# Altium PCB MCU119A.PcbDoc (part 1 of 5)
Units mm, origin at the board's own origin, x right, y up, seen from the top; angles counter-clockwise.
Board outline 58.62 x 144.37 mm, 6 copper layers (Top Signal, GND, Middle Signal, PWR, GND2, Bottom Signal), stack 1.566 mm thick; 316 components, 238 nets, 1210 pads, 1064 vias.
Unrouted connection lines stored in the file: 59.
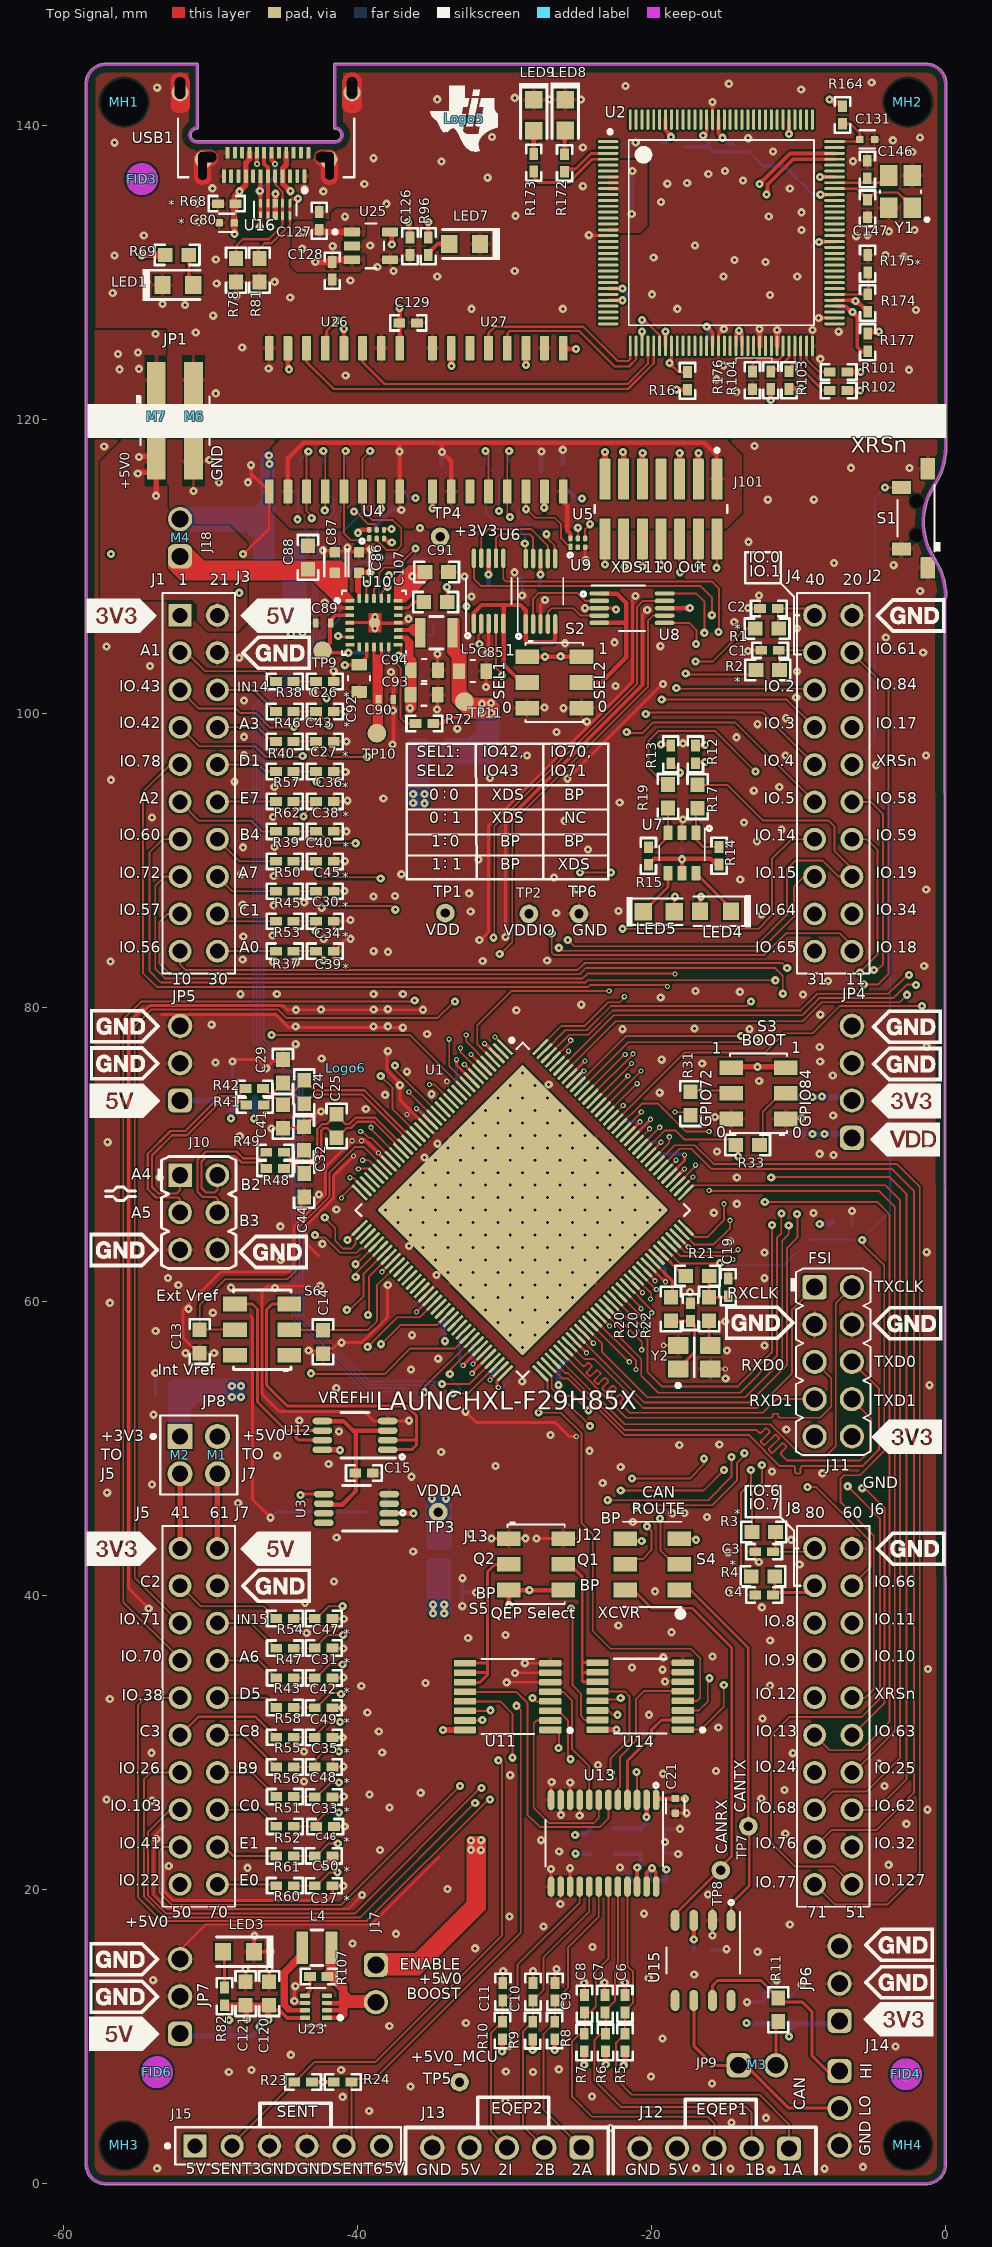
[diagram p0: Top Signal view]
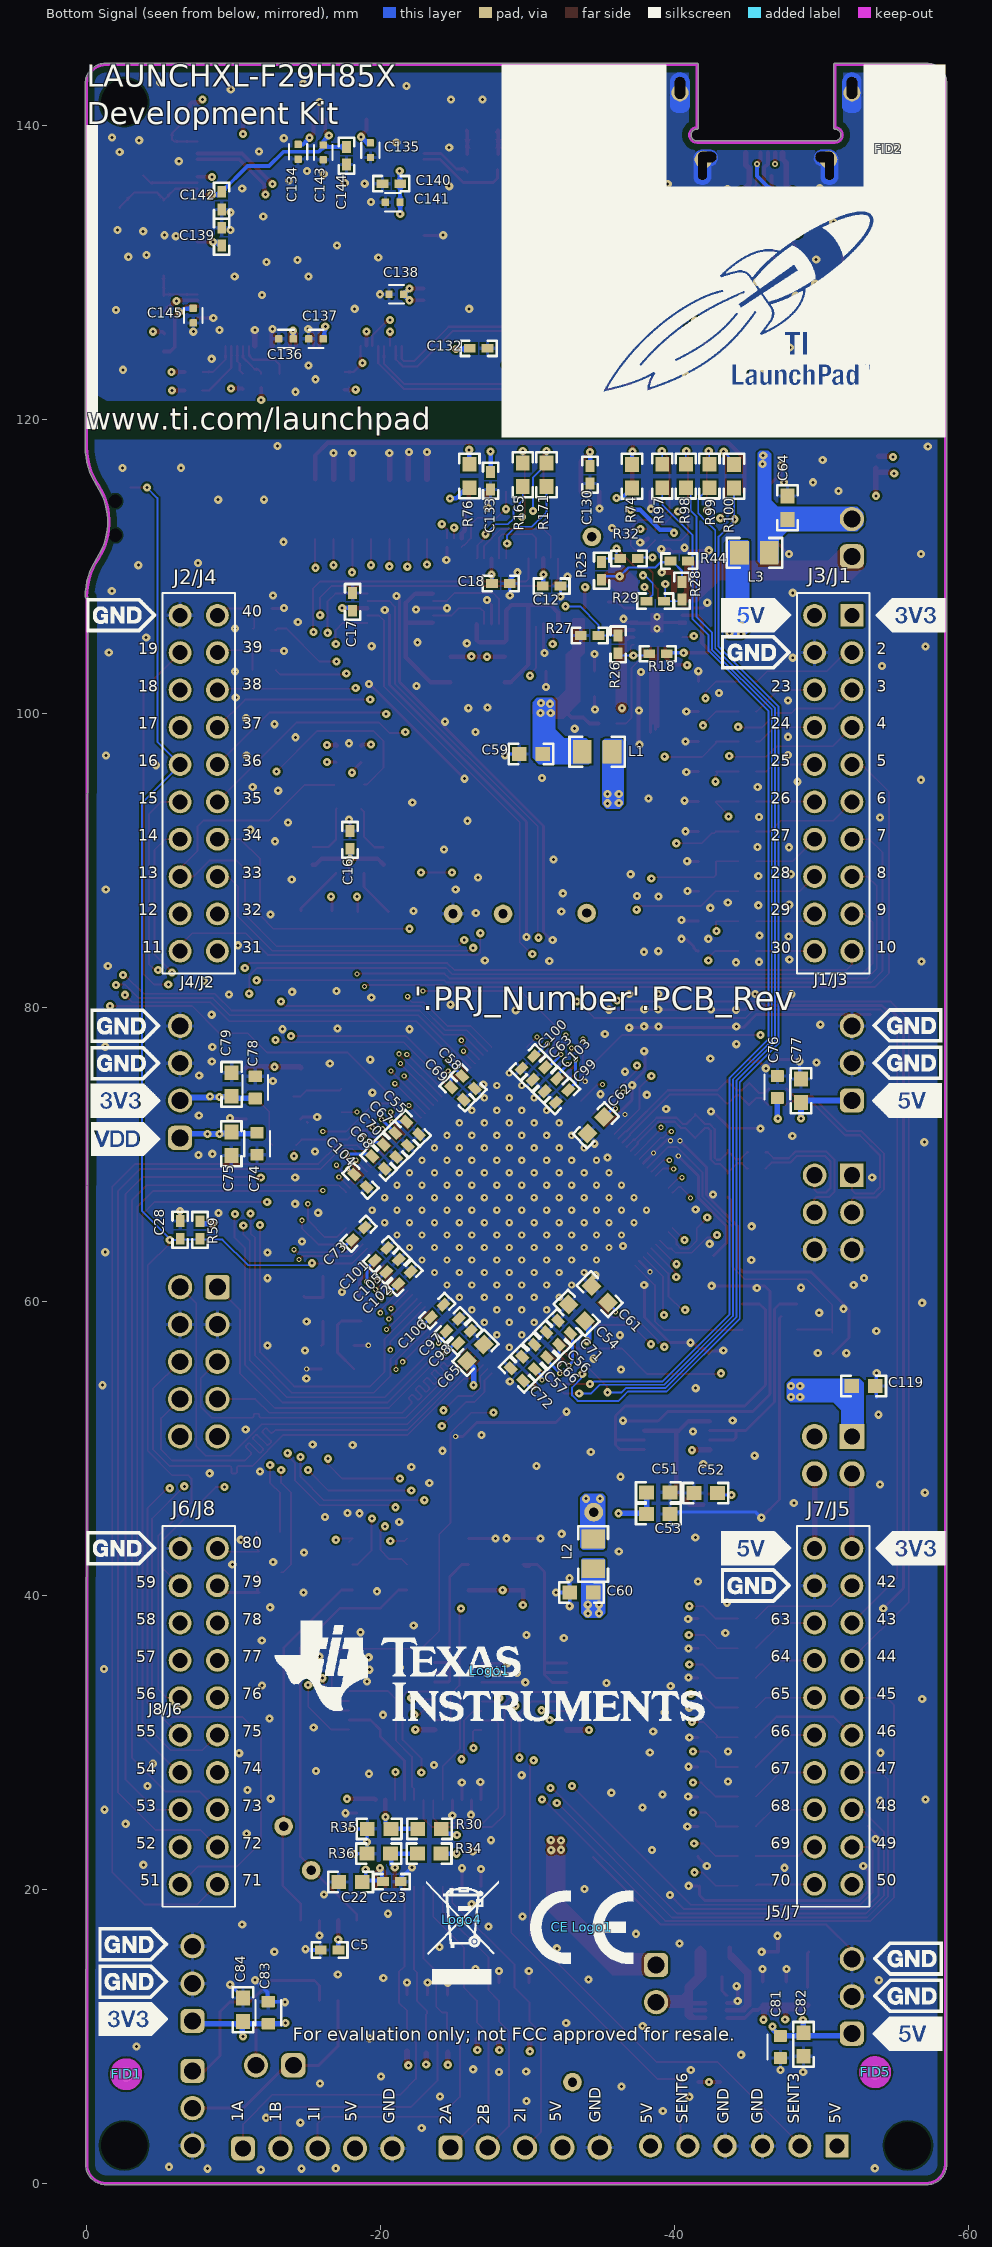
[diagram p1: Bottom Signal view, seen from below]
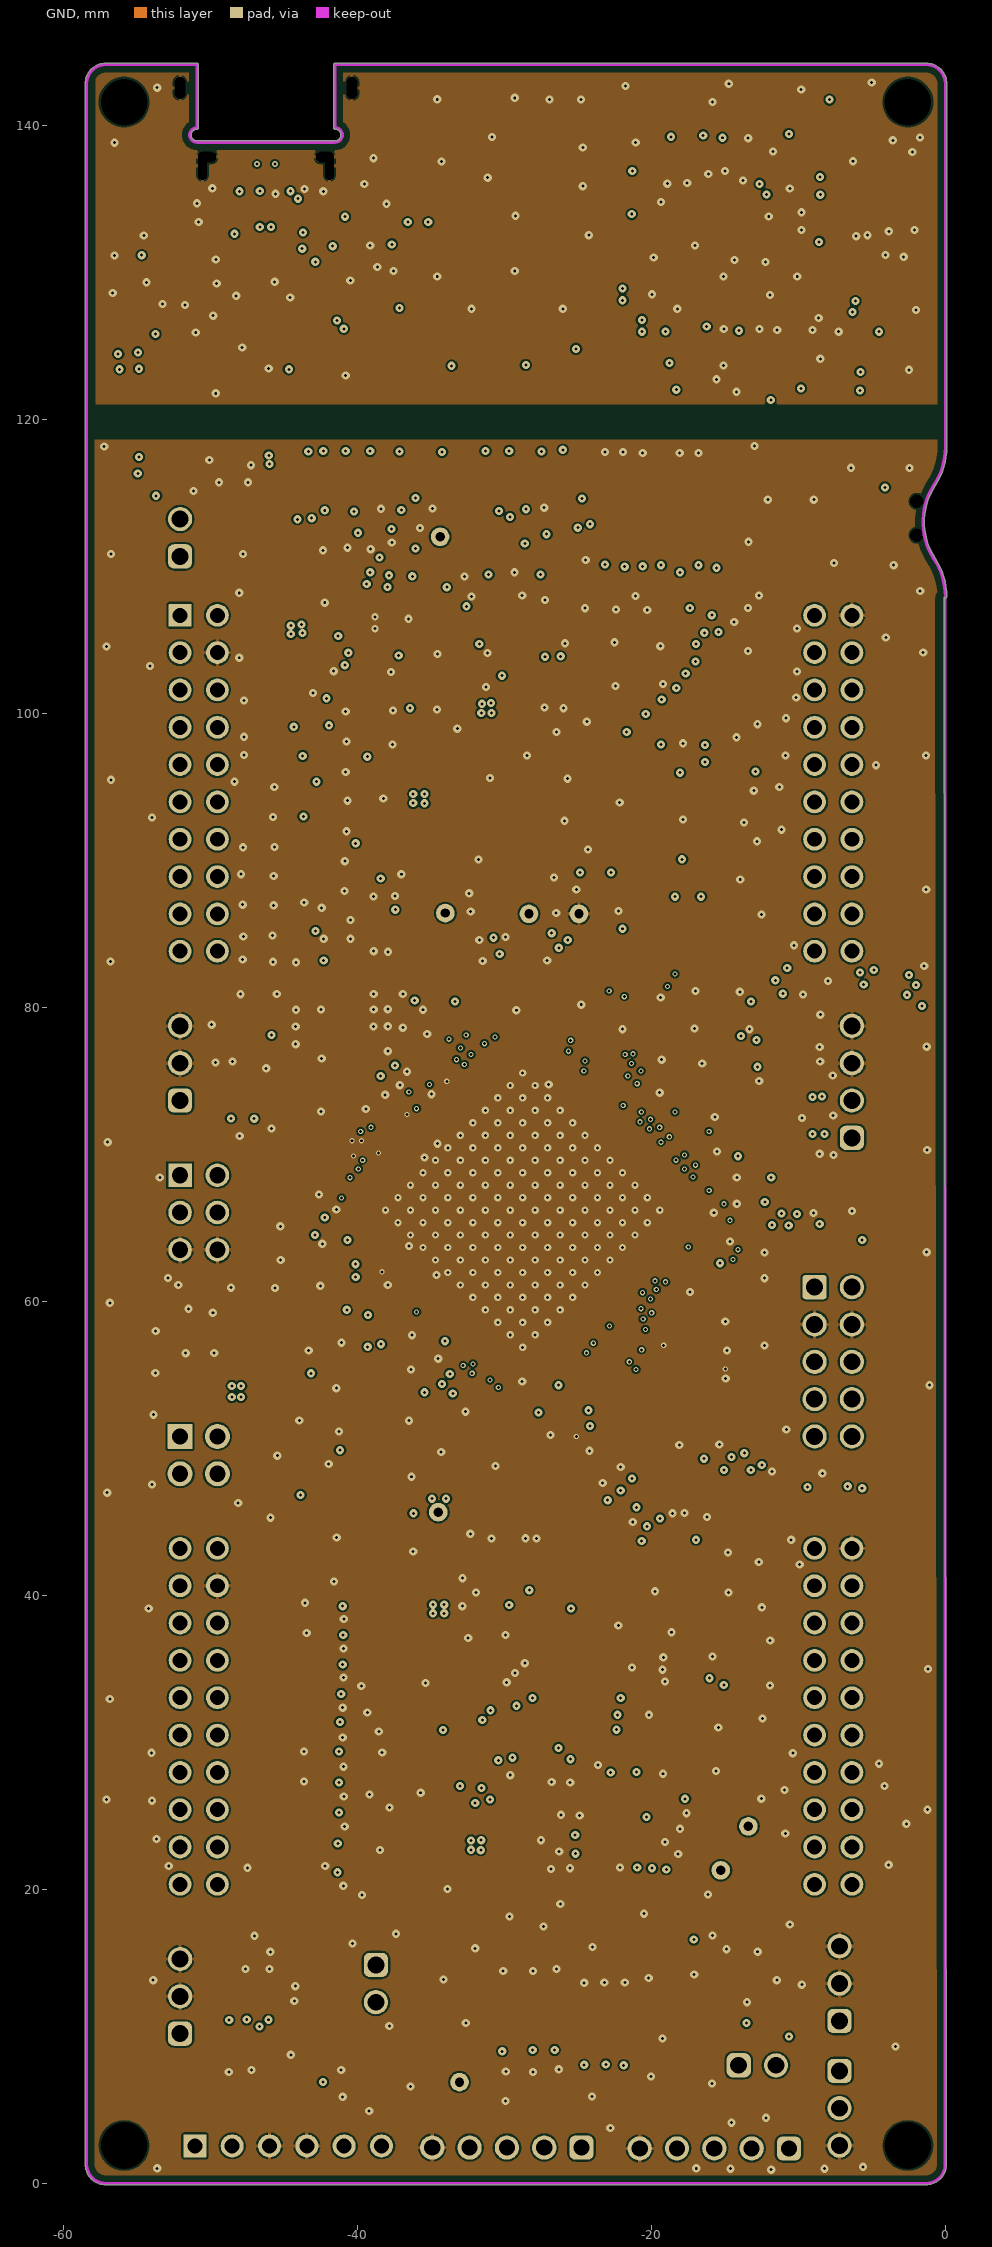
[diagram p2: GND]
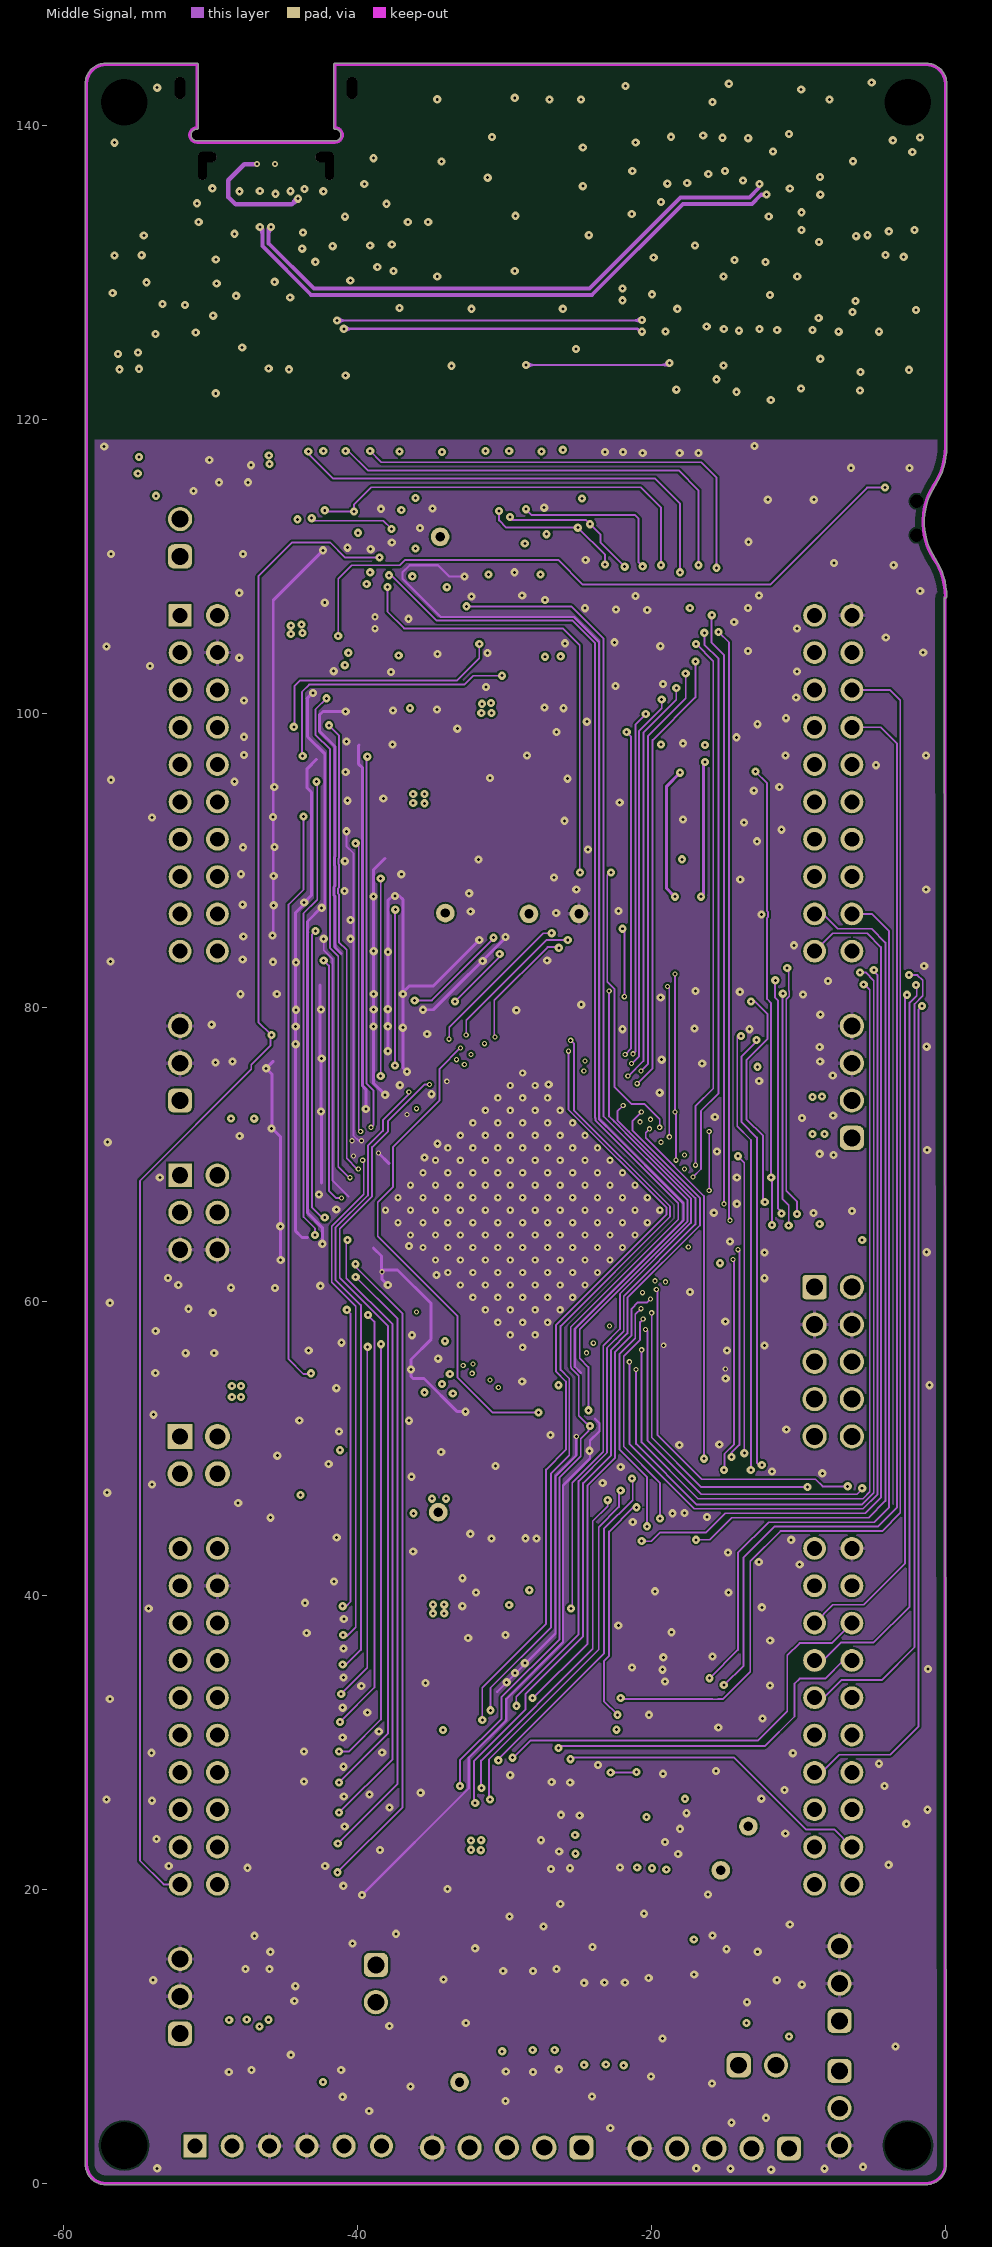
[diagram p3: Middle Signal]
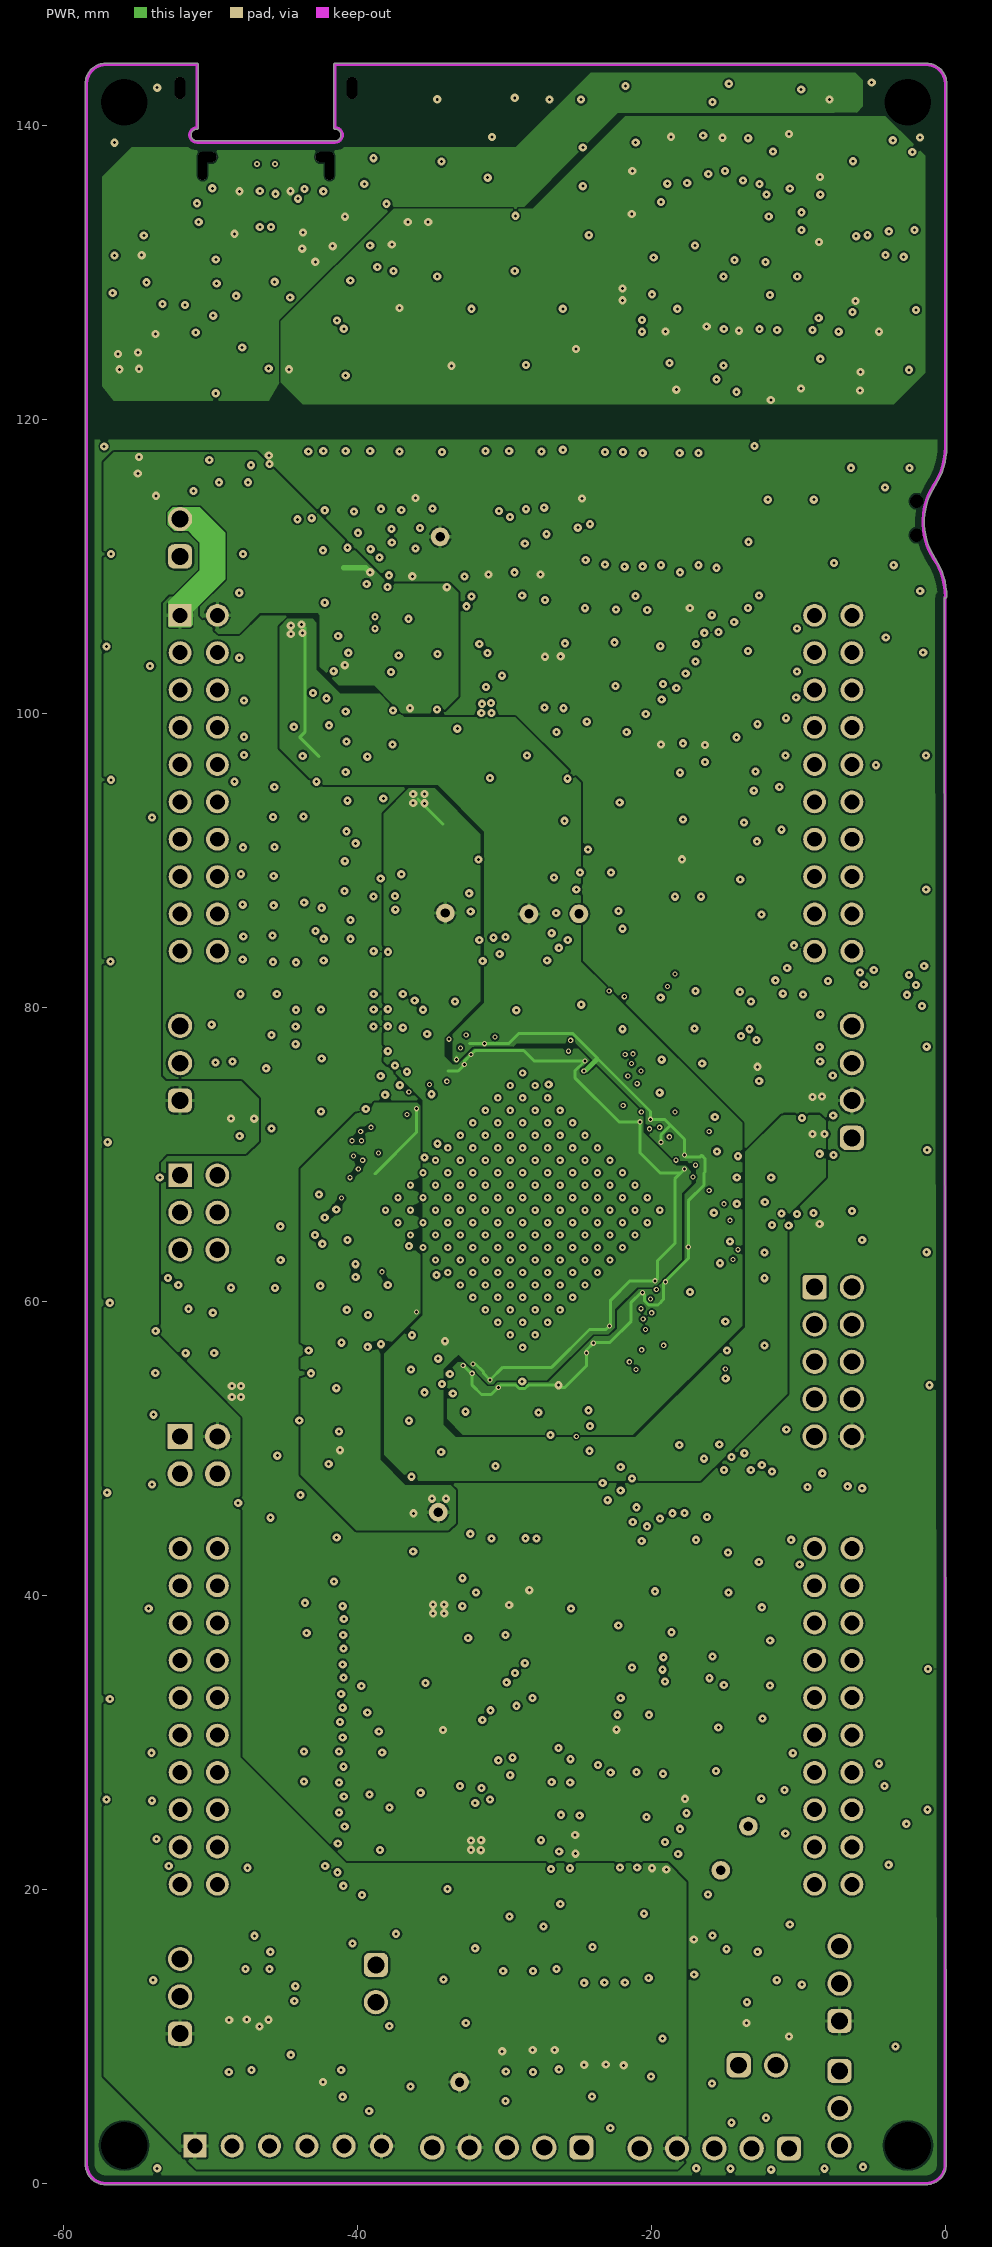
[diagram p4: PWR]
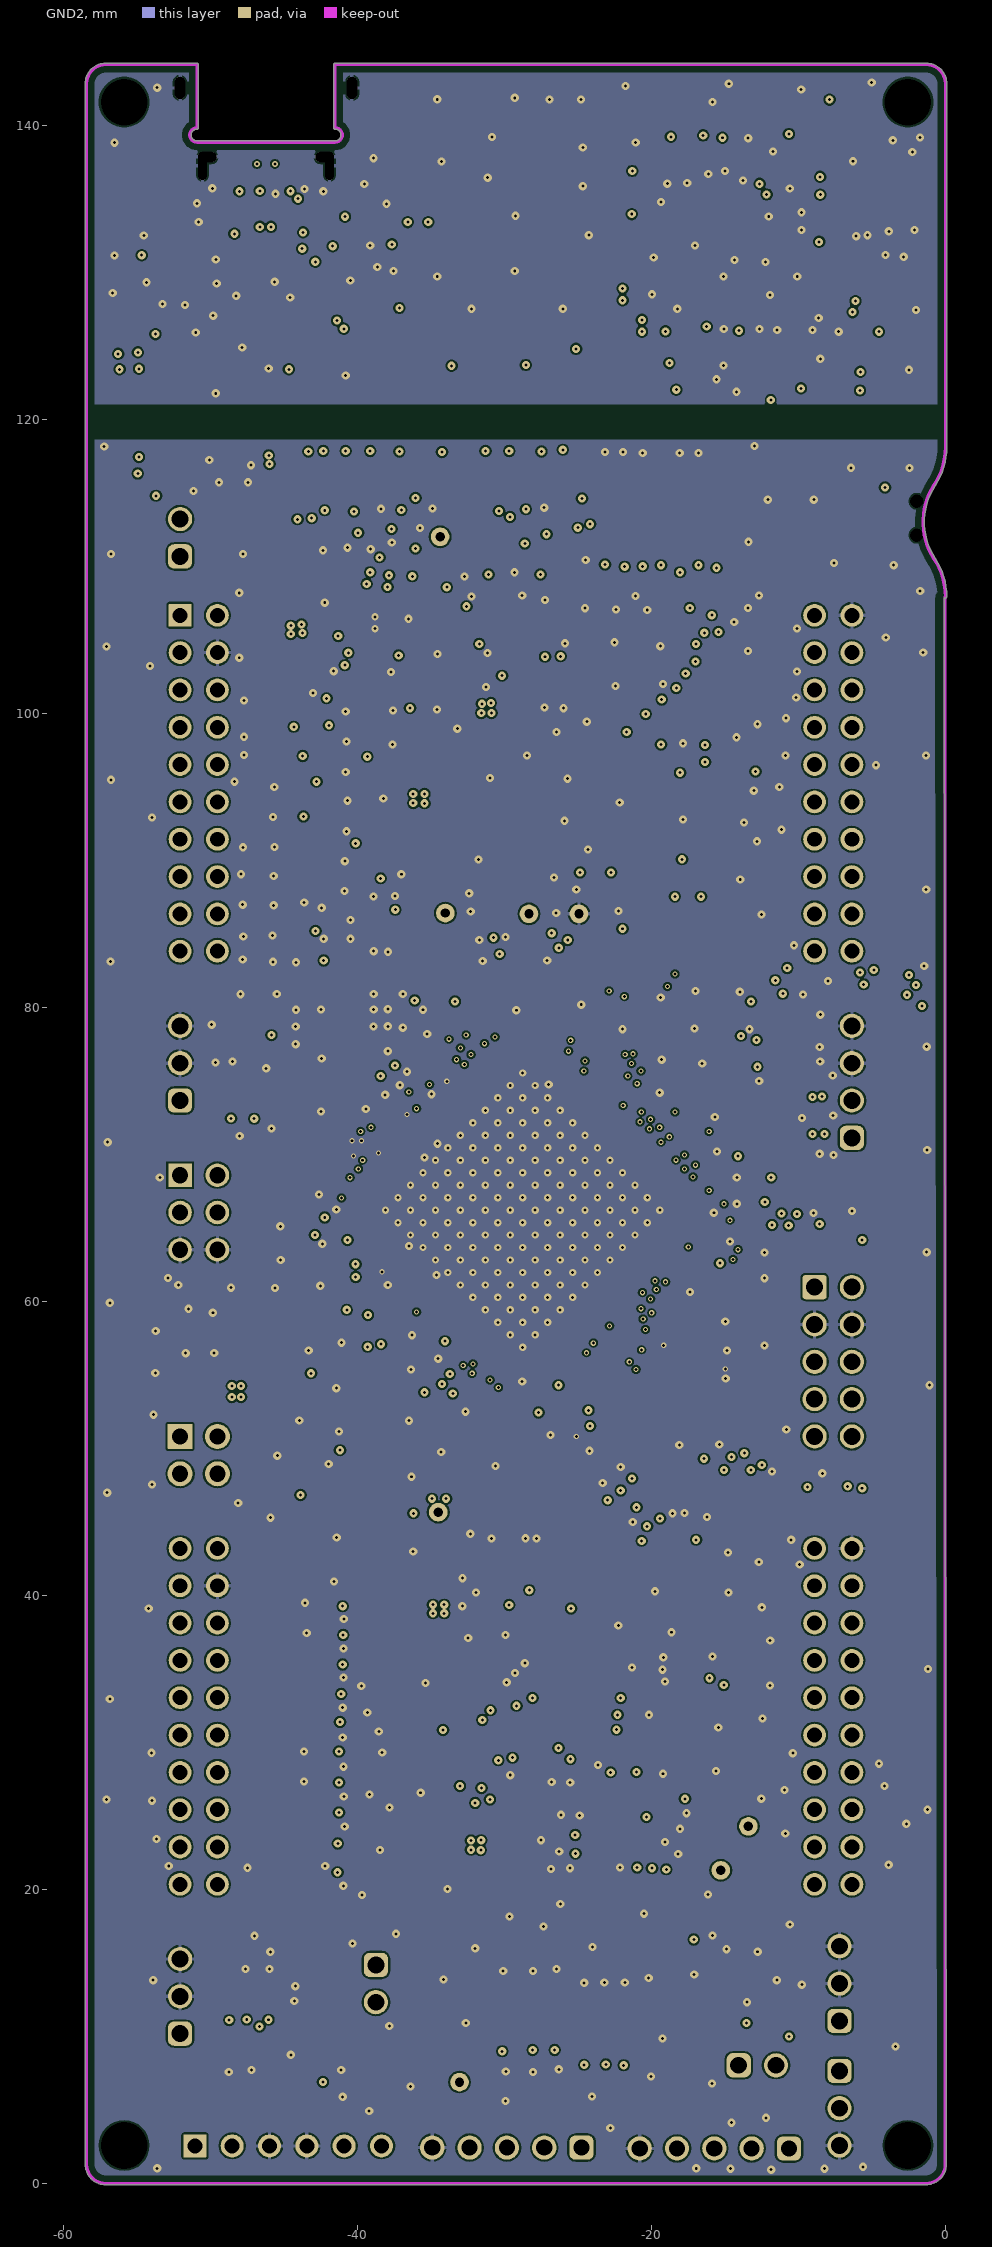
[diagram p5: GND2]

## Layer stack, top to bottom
Top Solder: solder mask 0.0102, Solder Resist, Dk 3.5
Top Signal: signal copper 0.0356
Dielectric 1: prepreg 0.1588, FR-4, Dk 4.2
GND: signal copper 0.0356
Dielectric 2: core 0.4089, FR-4, Dk 4.2
Middle Signal: signal copper 0.0356
Dielectric 3: prepreg 0.2169, FR-4, Dk 4.2
PWR: signal copper 0.0356
Dielectric 4: core 0.4089, FR-4, Dk 4.2
GND2: signal copper 0.0356
Dielectric 5: prepreg 0.1588, FR-4, Dk 4.2
Bottom Signal: signal copper 0.0356
Bottom Solder: solder mask 0.0102, Solder Resist, Dk 3.5

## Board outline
-57.141,-0.1 cw(c-57.141,1.27) -58.511,1.268 -58.511,1.27 -58.511,142.895 cw(c-57.141,142.895) -57.141,144.265 -50.911,144.265 cw(c-50.911,144.165) -50.811,144.165 -50.811,139.885 cw(c-50.911,139.885) -50.911,139.785 ccw(c-50.911,139.385) -51.311,139.385 ccw(c-50.911,139.385) -50.911,138.985 -41.511,138.985 -41.51,138.985 ccw(c-41.511,139.385) -41.111,139.385 ccw(c-41.511,139.385) -41.511,139.785 cw(c-41.511,139.885) -41.611,139.885 -41.611,144.135 -41.61,144.15 cw(c-41.511,144.165) -41.511,144.265 -1.261,144.265 cw(c-1.261,142.895) 0.109,142.895 0.109,118.13 cw(c-4.605,118.13) -0.669,115.535 ccw(c3.099,113.05) -0.669,110.565 cw(c-4.605,107.97) 0.109,107.97 cw(c0.009,107.97) -0.043,107.884 0.078,1.27 cw(c-1.292,1.27) -1.29,-0.1 -1.292,-0.1

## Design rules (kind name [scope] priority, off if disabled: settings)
AcuteAngle [All] p1: minimum=4.50000000000000E+0001 checktracksonly=TRUE
AcuteAngle AcuteAngle_poly [InPolygon] p2: minimum=4.50000000000000E+0001 checktracksonly=FALSE
AssemblyTestPointUsage [All] p1: valid=2
BoardOutlineClearance BoardOutlineClearance_USB1 [InComponent('USB1')] p1: gap=0 ignorepadtopadclearanceinfootprint=FALSE
BoardOutlineClearance BoardOutlineClearance_MountingHoles [OnCopper and InComponentClass('Mounting Holes')] p2: gap=1.016 ignorepadtopadclearanceinfootprint=FALSE
BoardOutlineClearance BoardOutlineClearance_Poly [OnCopper and IsPoly] p3: gap=0.635 ignorepadtopadclearanceinfootprint=FALSE
BoardOutlineClearance [OnCopper and Not InComponentClass('Logo') and not InComponentClass('FiducialMark') and not InRegion(1000,500,4000,800) and not InPoly] p4: gap=0.254 ignorepadtopadclearanceinfootprint=FALSE
Clearance Clearance_1 [InComponent('S1')OR InComponent('USB1') vs OnLayer('Keep-Out Layer')] p1: gap=0 ignorepadtopadclearanceinfootprint=FALSE
Clearance Poly [InPolygon] p2: gap=0.127 ignorepadtopadclearanceinfootprint=FALSE
Clearance "RJ45 pad" [InComponent('RJ1') OR InComponent('RJ2')] p3: gap=0.127 ignorepadtopadclearanceinfootprint=TRUE except(0: SMDPad-THPad)
Clearance Keepout [((IsTrack Or IsArc) And Not InPoly) And IsFree and IsKeepOut vs ((IsTrack Or IsArc) And Not InPoly) And IsFree and IsKeepOut] p4: gap=0.127 ignorepadtopadclearanceinfootprint=FALSE
Clearance USB1 [InComponent('USB1') vs OnLayer('Keep-Out Layer')] p5: gap=0.2 ignorepadtopadclearanceinfootprint=FALSE
Clearance ISVIA [ISVIA vs ISVIA] p6: gap=0.152 ignorepadtopadclearanceinfootprint=FALSE
Clearance Clearance_FiducialMark [IsKeepOut and InComponentClass('FiducialMark') vs IsPad and InComponentClass('FiducialMark')] p7: gap=0 ignorepadtopadclearanceinfootprint=FALSE
Clearance Clearance_Boardedge [All vs IsKeepOut] p8: gap=0.3 ignorepadtopadclearanceinfootprint=FALSE
Clearance INPOLYGON [InPolygon] p9: gap=0.303 ignorepadtopadclearanceinfootprint=FALSE
Clearance [All] p10: gap=0.127 ignorepadtopadclearanceinfootprint=FALSE except(0.094: Arc-Via Track-Via; 0.102: Arc-Arc Arc-Track Arc-SMDPad Track-Track Track-SMDPad)
ComponentClearance "ComponentClearance_overlay to overlay" [OnBottomSilkscreen vs OnTopSilkscreen] p1: gap=0 collisioncheckmode=3 verticalgap=0 showdistances=FALSE
ComponentClearance ComponentClearance_MountingHoles_FiducialMarks [InComponentClass('Mounting Holes') vs InComponentClass('FiducialMark')] p2: gap=0.254 collisioncheckmode=3 verticalgap=0.254 showdistances=FALSE
ComponentClearance ComponentClearance_Shunt [InComponentClass('Header') vs InComponentClass('Shunt')] p3: gap=0 collisioncheckmode=3 verticalgap=0 showdistances=FALSE
ComponentClearance ComponentClearance_Logo [InComponentClass('Logo')] p4: gap=0.254 collisioncheckmode=3 verticalgap=0.254 showdistances=FALSE
ComponentClearance ComponentClearance_ScrewToNut [(HasFootprint('NY PMS 440 0025 PH')) vs (HasFootprint('Keystone_1902C'))] p5: gap=0.127 collisioncheckmode=3 verticalgap=0.254 showdistances=FALSE
ComponentClearance ComponentClearance_MountingHoles [InComponentClass('Mounting Holes')] p6 off: gap=6.35 collisioncheckmode=3 verticalgap=2540 showdistances=FALSE
ComponentClearance ComponentClearance_SmallPassives [HasFootprint('0201*') or HasFootprint('0402*') or HasFootprint('0508') or HasFootprint('0603*') or HasFootprint('0612') or HasFootprint('0805*') or HasFootprint('0815*') or HasFootprint('0830*') or HasFootprint('1206*') or HasFootprint('1210*') or HasFootprint('1808*') or HasFootprint('1812*') or HasFootprint('1825*') or HasFootprint('2010*') or HasFootprint('2220*') or HasFootprint('2225*') or HasFootprint('2512*') or HasFootprint('2728*') or HasFootprint('3518*') vs HasFootprint('0201*') or HasFootprint('0402*') or HasFootprint('0508') or HasFootprint('0603*') or HasFootprint('0612') or HasFootprint('0805*') or HasFootprint('0815*') or HasFootprint('0830*') or HasFootprint('1206*') or HasFootprint('1210*') or HasFootprint('1808*') or HasFootprint('1812*') or HasFootprint('1825*') or HasFootprint('2010*') or HasFootprint('2220*') or HasFootprint('2225*') or HasFootprint('2512*') or HasFootprint('2728*') or HasFootprint('3518*')] p7 off: gap=0.254 collisioncheckmode=3 verticalgap=0 showdistances=FALSE
ComponentClearance ComponentClearance_THtoSMT [IsThruComponent vs IsSMTComponent] p8 off: gap=0.762 collisioncheckmode=3 verticalgap=0.762 showdistances=FALSE
ComponentClearance ComponentClearance_THtoTH [IsThruComponent vs IsThruComponent] p9 off: gap=0.762 collisioncheckmode=3 verticalgap=0.762 showdistances=FALSE
DiffPairsRouting USB_DiffPairsRouting_90 [InDifferentialPairClass('All Differential Pairs')] p1: maxlimit=2.54 minlimit=0.127 mostfreqgap=0.152 toplayer_minwidth=0.102 toplayer_maxwidth=0.381 toplayer_prefwidth=0.155 midlayer1_minwidth=0.152 midlayer1_maxwidth=0.381 midlayer1_prefwidth=0.155 midlayer2_minwidth=0.152 midlayer2_maxwidth=0.381 midlayer2_prefwidth=0.155 midlayer3_minwidth=0.152 midlayer3_maxwidth=0.381 midlayer3_prefwidth=0.155 midlayer4_minwidth=0.152 midlayer4_maxwidth=0.381 midlayer4_prefwidth=0.155 bottomlayer_minwidth=0.102 bottomlayer_maxwidth=0.381 bottomlayer_prefwidth=0.155 maxuncoupledlength=25.4
DiffPairsRouting [All] p2: maxlimit=0.254 minlimit=0.152 mostfreqgap=0.152 toplayer_minwidth=0.102 toplayer_maxwidth=0.157 toplayer_prefwidth=0.124 midlayer1_minwidth=0.124 midlayer1_maxwidth=0.157 midlayer1_prefwidth=0.124 midlayer2_minwidth=0.124 midlayer2_maxwidth=0.381 midlayer2_prefwidth=0.124 midlayer3_minwidth=0.124 midlayer3_maxwidth=0.381 midlayer3_prefwidth=0.124 midlayer4_minwidth=0.124 midlayer4_maxwidth=0.381 midlayer4_prefwidth=0.124 bottomlayer_minwidth=0.102 bottomlayer_maxwidth=0.157 bottomlayer_prefwidth=0.124 maxuncoupledlength=12.7
FabricationTestPointUsage TestPointUsage [All] p1: valid=2 allowmultiple=FALSE
FabricationTestpoint Testpoint [All] p1: side=3 testpointundercomponent=TRUE minsize=1.016 maxsize=2.54 preferedsize=1.524 minholesize=0 maxholesize=1.016 preferedholesize=0.813 testpointgrid=0.025 allowsidetop=TRUE allowsidebottom=TRUE usegrid=TRUE gridtolerance=0
FanoutControl Fanout_LCC [IsLCC] p1: bgadir=Out bgaviamode=Centered fanoutstyle=Auto fanoutdirection=Alternating viagrid=0.025 // Fanout_LCC (Default Rule)
FanoutControl Fanout_BGA [IsBGA] p2: bgadir=Out bgaviamode=Centered fanoutstyle=Auto fanoutdirection=Alternating viagrid=0.025 // Fanout_BGA (Default Rule)
FanoutControl Fanout_Default [All] p4: bgadir=Out bgaviamode=Centered fanoutstyle=Auto fanoutdirection=Alternating viagrid=0.025 // Fanout_Default (Default Rule)
FanoutControl Fanout_Small [(CompPinCount < 5)] p5: bgadir=Out bgaviamode=Centered fanoutstyle=Auto fanoutdirection=OutThenIn viagrid=0.025 // Fanout_Small (Default Rule)
HoleSize [All] p1: absolutevalues=TRUE maxlimit=6.375 minlimit=0.2 maxpercent=80.000 minpercent=20.000
HoleToHoleClearance HoleToHoleClearance_USB1 [InComponent('USB1') vs InComponent('USB1')] p1: gap=0 allowstackedmicrovias=TRUE
HoleToHoleClearance [All] p2: gap=0.254 allowstackedmicrovias=TRUE
MatchedLengths FSIRX [InNetClass('FSIRX')] p1: tolerance=0.635 checknetsindiffpair=FALSE checkdiffpairvsdiffpair=TRUE checkxsignals=TRUE checkothers=TRUE
MatchedLengths FSITX [InNetClass('FSITX')] p2: tolerance=0.635 checknetsindiffpair=FALSE checkdiffpairvsdiffpair=TRUE checkxsignals=TRUE checkothers=TRUE
MinimumAnnularRing MinimumAnnularRing_ThermalPadVias [IsVia and InAnyComponent] p1: minimumring=0.076
MinimumAnnularRing MinimumAnnularRing_usb1 [InComponent('USB1')] p2: minimumring=0
MinimumAnnularRing [All] p3: minimumring=0.076
MinimumSolderMaskSliver MinimumSolderMaskSliver_Logo [InComponentClass('Logo') vs InComponentClass('Logo')] p1: minsoldermaskwidth=0.018
MinimumSolderMaskSliver [All] p2: minsoldermaskwidth=0.076
PlaneClearance PlaneClearance_Via [IsVia] p1: clearance=0.254
PlaneClearance [All] p2: clearance=0.254
PlaneConnect [All] p1: planeconnectstyle=Relief reliefexpansion=0.254 reliefentries=4 reliefconductorwidth=0.635 reliefairgap=0.254
PolygonConnect PolygonConnect_via [IsVia] p1: connectstyle=Direct reliefconductorwidth=0.254 reliefentries=4 polygonreliefangle="90 Angle" airgapwidth=0.254
PolygonConnect PolygonConnect_GND_under_device [Name = 'TOP_SIGNAL_GND_P125'] p2: connectstyle=Direct reliefconductorwidth=0.254 reliefentries=4 polygonreliefangle="90 Angle" airgapwidth=0.127
PolygonConnect PolygonConnect_via_VDD [Name = 'PWR_VDD_P012'] p3: thpad.connectstyle=Relief thpad.reliefconductorwidth=0.254 thpad.reliefentries=4 thpad.polygonreliefangle="90 Angle" thpad.airgapwidth=0.127 smdpad.connectstyle=Relief smdpad.reliefconductorwidth=0.254 smdpad.reliefentries=4 smdpad.polygonreliefangle="90 Angle" smdpad.airgapwidth=0.127 via.connectstyle=Direct via.reliefconductorwidth=0.254 via.reliefentries=4 via.polygonreliefangle="90 Angle" via.airgapwidth=0.127
PolygonConnect PolygonConnect_via_VDDIO [Name = 'PWR_VDDIO_P129'] p4: thpad.connectstyle=Relief thpad.reliefconductorwidth=0.254 thpad.reliefentries=4 thpad.polygonreliefangle="90 Angle" thpad.airgapwidth=0.127 smdpad.connectstyle=Relief smdpad.reliefconductorwidth=0.254 smdpad.reliefentries=4 smdpad.polygonreliefangle="90 Angle" smdpad.airgapwidth=0.127 via.connectstyle=Direct via.reliefconductorwidth=0.254 via.reliefentries=4 via.polygonreliefangle="90 Angle" via.airgapwidth=0.127
PolygonConnect [All] p5: connectstyle=Relief reliefconductorwidth=0.254 reliefentries=4 polygonreliefangle="90 Angle" airgapwidth=0.127
RoutingVias ThermalPadVias [IsVia and InAnyComponent] p1: holewidth=0.203 width=0.559 viastyle="Through Hole" minholewidth=0.2 minwidth=0.356 maxholewidth=0.203 maxwidth=0.559
RoutingVias [All] p2: holewidth=0.203 width=0.559 viastyle="Through Hole" minholewidth=0.2 minwidth=0.356 maxholewidth=0.203 maxwidth=0.559
ShortCircuit ShortCircuit_RJ45 [InComponent('RJ1') And IsThruPin Or InComponent('RJ2') And IsThruPin] p1: allowed=TRUE
ShortCircuit [All] p2: allowed=FALSE
SilkToBoardRegionClearance [Not ((IsComment or IsDesignator) And (Hide <> 'False')) and not InRegion(1000,500,4000,800)] p1:
SilkToSilkClearance SilkToSilkClearance_Pb-FreeLogo [(HasFootprint('Pb-Free_Overlay_Medium') OR HasFootprint('Pb-Free_Overlay_Small')) vs (HasFootprint('Pb-Free_Overlay_Medium') OR HasFootprint('Pb-Free_Overlay_Small'))] p1: silktosilkclearance=0
SilkToSilkClearance [All] p2: silktosilkclearance=0.076
SilkToSolderMaskClearance SilkToComponentPadClearance [(IsPad or IsFill or IsRegion) and InAnycomponent] p1: minsilkscreentomaskgap=0.076 clearancetoexposedcopper=TRUE
SilkToSolderMaskClearance "Silk to Solder Mask Opening" [All] p2: minsilkscreentomaskgap=0.076 clearancetoexposedcopper=TRUE
SolderMaskExpansion [All] p1: expansion=0.05 istentingtop=FALSE
UnRoutedNet [All] p1: checkbadconnections=TRUE
Width USB_width [InNetClass('Analog')] p1: maxlimit=0.155 minlimit=0.102 preferedwidth=0.152
Width [All] p2: maxlimit=0.381 minlimit=0.102 preferedwidth=0.127 checkconnectedcopper=TRUE
11 further rules are at their usual default settings.

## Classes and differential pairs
component class MCU119A_F29H85X_Device: C28 C54 C55 C56 C57 C58 C59 C60 C61 C62 C63 C64 C65 C66 C67 C68 C69 C70 C71 C72 C73 C97 C98 C99 C100 C101 C102 C103 C104 C105 C106 L1 L2 L3 R44 R59 S1
component class MCU119A_XDS110_MCU: C129 C130 C131 C132 C133 C134 C135 C136 C137 C138 C139 C140 C141 C142 C143 C144 C145 C146 C147 J101 LED8 LED9 R16 R74 R76 R97 R98 R99 R100 R101 R102 R103 R104 R164 R165 R171 R172 R173 R174 R175 R176 R177 U2 U4 U5 U26 U27 Y1
net class FSITX: GPIO49_FSITXD0 GPIO50_FSITXD1 GPIO51_FSITXCLK
net class FSIRX: GPIO52_FSIRXD0 GPIO53_FSIRXD1 GPIO54_FSIRXCLK
component class MCU119A_USB_and_Power: C74 C75 C76 C77 C78 C79 C80 C81 C82 C83 C84 C85 C86 C87 C88 C89 C90 C91 C92 C93 C94 C107 C119 C120 C121 C126 C127 C128 J17 J18 JP1 JP4 JP5 JP6 JP7 JP10 L4 L5 LED1 LED3 LED7 M4 M6 M7 R18 R25 R26 R27 R28 R29 R32 R68 R69 R72 R78 R81 R82 R96 R107 TP1 TP2 TP3 TP4 TP5 TP6 TP9 TP10 TP11 U10 U16 U23 U25 USB1
component class MCU119A_ADC: C13 C14 C15 C24 C25 C26 C27 C29 C30 C31 C32 C33 C34 C35 C36 C37 C38 C39 C40 C41 C42 C43 C44 C45 C46 C47 C48 C49 C50 C51 C52 C53 R37 R38 R39 R40 R41 R42 R43 R45 R46 R47 R48 R49 R50 R51 R52 R53 R54 R55 R56 R57 R58 R60 R61 R62 S6 U1 U3 U12
component class MCU119A_Connectors: C1 C2 C3 C4 C5 C6 C7 C8 C9 C10 C11 J1/J3 J4/J2 J5/J7 J8/J6 J10 J11 J12 J13 J14 J15 JP8 JP9 M1 M2 M3 R1 R2 R3 R4 R5 R6 R7 R8 R9 R10 R11 R23 R24 TP7 TP8 U15
component class MCU119A_AltRouting_Misc: C12 C16 C17 C18 C19 C20 C21 C22 C23 LED4 LED5 R12 R13 R14 R15 R17 R19 R20 R21 R22 R30 R31 R33 R34 R35 R36 S2 S3 S4 S5 U6 U7 U8 U9 U11 U13 U14 Y2
component class Header: J10 J11 J12 J13 J14 J17 J18 JP1 JP4 JP5 JP6 JP7 JP9 JP10
component class AssemblyNote: ZZ1 ZZ2 ZZ3
component class FiducialMark: FID1 FID2 FID3 FID4 FID5 FID6
component class MCU119A_Hardware: "CE Logo1" FID1 FID2 FID3 FID4 FID5 FID6 Logo1 Logo3 Logo4 Logo5 Logo6 MH1 MH2 MH3 MH4 ZZ1 ZZ2 ZZ3
component class Logo: Logo1 Logo5 Logo6
component class Shunt: M1 M2 M3 M4 M6 M7
differential pair MCU_B2B3: +MCU_B2B3_P -MCU_B2B3_N
differential pair MCU_A4A5: +MCU_A4A5_P -MCU_A4A5_N
differential pair ADCINB2B3: +ADCINB2B3_P -ADCINB2B3_N
differential pair ADCINA4A5: +ADCINA4A5_P -ADCINA4A5_N
differential pair USB_D: +USB_D_P -USB_D_N

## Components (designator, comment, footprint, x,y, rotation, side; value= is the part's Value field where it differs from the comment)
C1 "885012205037" 0402 -11.913,104.318 r180 top value=0.1uF
C2 "885012205037" 0402 -11.989,107.163 r180 top value=0.1uF
C3 "885012205037" 0402 -12.319,42.977 r180 top value=0.1uF
C4 "885012205037" 0402 -12.319,40.03 r180 top value=0.1uF
C5 "885012205037" 0402 -16.517,15.875 r180 bottom value=0.1uF
C6 "885012205061" 0402 -21.793,12.217 r90 top value=1000pF
C7 "885012205061" 0402 -23.139,12.217 r90 top value=1000pF
C8 "885012205061" 0402 -24.54,12.217 r90 top value=1000pF
C9 "885012205061" 0402 -26.543,13.03 r90 top value=1000pF
C10 "885012205061" 0402 -28.042,13.03 r90 top value=1000pF
C11 "885012205061" 0402 -30.099,13.03 r90 top value=1000pF
C12 "885012205037" 0402 -31.623,108.687 r0 bottom value=0.1uF
C13 "885012106018" 0603 -50.724,57.276 r270 top value=4.7uF
C14 "885012106018" 0603 -42.342,57.252 r270 top value=4.7uF
C15 "0402ZD106MAT2A" 0402_080 -39.548,48.336 r0 top value=10uF
C16 "885012205037" 0402 -17.907,91.415 r90 bottom value=0.1uF
C17 "885012205037" 0402 -18.085,107.614 r270 bottom value=0.1uF
C18 "885012205037" 0402 -28.169,108.864 r180 bottom value=0.1uF
C19 "C0402C120J3GACAUTO" 0402 -14.757,60.96 r90 top value=12pF
C20 "C0402C120J3GACAUTO" 0402 -17.323,59.284 r90 top value=12pF
C21 "885012205018" FP-885012205018_0402-MFG -18.364,25.679 r270 top value=100nF
C22 "C0603C104K8RACTU" 0603 -17.944,20.505 r0 bottom value=0.1uF
C23 "885012205061" 0402 -20.752,20.523 r180 bottom value=1000pF
C24 "C0603C102J5GACTU" 0603 -43.612,74.27 r270 top value=1nF
C25 "C0603C102J5GACTU" 0603 -41.402,71.949 r270 top value=1nF
C26 "GRM1555C1H331JA01D" 0402 -42.206,102.191 r0 top value=330pF
C27 "GRM1555C1H331JA01D" 0402 -42.206,98.114 r0 top value=330pF
C28 "GCM1555C1H201FA16D" FP-GCM1555C1H201FA16D_0402-MFG -6.35,64.881 r90 bottom value=200pF
C29 "CL05B222JB5NNNC" 0603 -45.069,75.667 r270 top value=2.2nF
C30 "GRM1555C1H331JA01D" 0402 -42.206,87.921 r0 top value=330pF
C31 "GRM1555C1H331JA01D" 0402 -42.291,36.424 r0 top value=330pF
C32 "CL05B222JB5NNNC" 0603 -43.637,71.095 r270 top value=2.2nF
C33 "GRM1555C1H331JA01D" 0402 -42.291,26.289 r0 top value=330pF
C34 "GRM1555C1H331JA01D" 0402 -42.206,85.883 r0 top value=330pF
C35 "GRM1555C1H331JA01D" 0402 -42.291,30.328 r0 top value=330pF
C36 "GRM1555C1H331JA01D" 0402 -42.206,96.075 r0 top value=330pF
C37 "GRM1555C1H331JA01D" 0402 -42.291,20.244 r0 top value=330pF
C38 "GRM1555C1H331JA01D" 0402 -42.206,94.037 r0 top value=330pF
C39 "GRM1555C1H331JA01D" 0402 -42.206,83.844 r0 top value=330pF
C40 "GRM1555C1H331JA01D" 0402 -42.206,91.998 r0 top value=330pF
C41 "CL05B222JB5NNNC" 0603 -45.06,72.593 r90 top value=2.2nF
C42 "GRM1555C1H331JA01D" 0402 -42.291,34.392 r0 top value=330pF
C43 "GRM1555C1H331JA01D" 0402 -42.206,100.152 r0 top value=330pF
C44 "CL05B222JB5NNNC" 0603 -43.612,67.918 r90 top value=2.2nF
C45 "GRM1555C1H331JA01D" 0402 -42.206,89.96 r0 top value=330pF
C46 "GRM1555C1H331JA01D" 0402 -42.195,24.268 r0 top value=330pF
C47 "GRM1555C1H331JA01D" 0402 -42.291,38.43 r0 top value=330pF
C48 "GRM1555C1H331JA01D" 0402 -42.291,28.321 r0 top value=330pF
C49 "GRM1555C1H331JA01D" 0402 -42.291,32.36 r0 top value=330pF
C50 "GRM1555C1H331JA01D" 0402 -42.291,22.276 r0 top value=330pF
C51 "C0603C104K8RACTU" 0603 -38.887,47.015 r180 bottom value=0.1uF
C52 "C0603C105Z9VACTU" 0603 -42.113,46.965 r0 bottom value=1uF
C53 "C0603C225K9PACTU" 0603 -38.887,45.542 r180 bottom value=2.2uF
C54 "GRM188R61C106KAALD" 0603 -33.325,59.233 r45 bottom value=10uF
C55 "885012205037" 0402 -22.174,71.806 r225 bottom value=0.1uF
C56 "885012205037" 0402 -31.699,57.48 r45 bottom value=0.1uF
C57 "885012205037" 0402 -30.048,55.829 r45 bottom value=0.1uF
C58 "885012205037" 0402 -25.975,74.925 r225 bottom value=0.1uF
C59 "GRM188R61C106KAALD" 0603 -30.223,97.257 r0 bottom value=10uF
C60 "885012106018" 0603 -33.655,40.208 r0 bottom value=2.2uF
C61 "885012106018" 0603 -34.89,60.506 r45 bottom value=2.2uF
C62 "885012106018" 0603 -34.633,71.991 r315 bottom value=2.2uF
C63 "885012205037" 0402 -30.776,75.509 r315 bottom value=0.1uF
C64 "885012106018" 0603 -47.676,114.021 r90 bottom value=2.2uF
C65 "885012106018" 0603 -26.441,56.515 r135 bottom value=2.2uF
C66 "885012205037" 0402 -30.886,56.642 r45 bottom value=0.1uF
C67 "885012205037" 0402 -21.412,71.044 r225 bottom value=0.1uF
C68 "885012205037" 0402 -19.837,69.457 r225 bottom value=0.1uF
C69 "885012205037" 0402 -25.222,74.168 r225 bottom value=0.1uF
C70 "885012205037" 0402 -20.625,70.256 r225 bottom value=0.1uF
C71 "885012205037" 0402 -32.487,58.268 r45 bottom value=0.1uF
C72 "885012205037" 0402 -29.261,55.042 r45 bottom value=0.1uF
C73 "885012205037" 0402 -18.491,64.618 r135 bottom value=0.1uF
C74 "CC0603KRX5R6BB106" FP-CC0603KRX5R6BB106_0603-MFG -11.582,70.739 r90 bottom value=10¦ÌF
C75 "C0603C104K8RACTU" 0603 -9.83,70.739 r90 bottom value=0.1uF
C76 "CC0603KRX5R6BB106" FP-CC0603KRX5R6BB106_0603-MFG -46.99,74.6 r270 bottom value=10¦ÌF
C77 "C0603C104K8RACTU" 0603 -48.595,74.346 r90 bottom value=0.1uF
C78 "CC0603KRX5R6BB106" FP-CC0603KRX5R6BB106_0603-MFG -11.455,74.574 r270 bottom value=10¦ÌF
C79 "C0603C104K8RACTU" 0603 -9.855,74.778 r90 bottom value=0.1uF
C80 "885012205064" FP-885012205064_0402-MFG -48.885,133.403 r0 top value=3.3nF
C81 "CC0603KRX5R6BB106" FP-CC0603KRX5R6BB106_0603-MFG -47.193,9.271 r90 bottom value=10¦ÌF
C82 "C0603C104K8RACTU" 0603 -48.768,9.449 r270 bottom value=0.1uF
C83 "CC0603KRX5R6BB106" FP-CC0603KRX5R6BB106_0603-MFG -12.344,11.608 r270 bottom value=10¦ÌF
C84 "C0603C104K8RACTU" 0603 -10.617,11.811 r90 bottom value=0.1uF
C85 "CGA4J3X7S1A106K125AE" FP-CGA4J3X7S1A106K125AE_0805-MFG -32.156,102.904 r0 top
C86 "CGA3E3X7S1A225K080AB" FP-CGA3E3X7S1A225K080AB_0603-MFG -39.878,110.287 r270 top value=2.2¦ÌF
C87 "CGA3E3X7S1A225K080AB" FP-CGA3E3X7S1A225K080AB_0603-MFG -41.529,110.287 r270 top value=2.2¦ÌF
C88 "C0603C104K8RACTU" 0603 -43.358,110.642 r270 top value=0.1uF
C89 "GCM155C71A105KE38D" 0402_070 -42.315,106.183 r180 top value=1uF
C90 "GCM155C71A105KE38D" 0402_070 -38.049,100.965 r0 top value=1uF
C91 "C0603C104K8RACTU" 0603 -34.6,109.653 r0 top value=0.1uF
C92 "CGA4J3X7S1A106K125AE" FP-CGA4J3X7S1A106K125AE_0805-MFG -39.878,102.413 r270 top
C93 "CGA4J3X7S1A106K125AE" FP-CGA4J3X7S1A106K125AE_0805-MFG -35.458,101.295 r0 top
C94 "CGA4J3X7S1A106K125AE" FP-CGA4J3X7S1A106K125AE_0805-MFG -35.433,102.972 r0 top
C97 "885012205037" 0402 -24.892,58.395 r135 bottom value=0.1uF
C98 "885012205037" 0402 -25.705,57.582 r135 bottom value=0.1uF
C99 "885012205037" 0402 -32.334,73.973 r315 bottom value=0.1uF
C100 "885012205037" 0402 -29.997,76.283 r315 bottom value=0.1uF
C101 "885012205037" 0402 -20.015,63.221 r135 bottom value=0.1uF
C102 "885012205037" 0402 -21.606,61.613 r135 bottom value=0.1uF
C103 "885012205037" 0402 -31.572,74.727 r315 bottom value=0.1uF
C104 "885012205037" 0402 -18.618,68.224 r225 bottom value=0.1uF
C105 "885012205037" 0402 -20.789,62.433 r135 bottom value=0.1uF
C106 "885012205037" 0402 -23.841,59.363 r135 bottom value=0.1uF
C107 "GRM188R61A226ME15D" 0603 -34.671,107.594 r0 top value=22uF
C119 "GRM188R61C475KAAJ" 0603 -52.857,54.254 r180 bottom value=4.7uF
C120 "GRM188R61A226ME15D" 0603 -45.999,12.903 r90 top value=22uF
C121 "GRM188R61A226ME15D" 0603 -47.6,12.903 r90 top value=22uF
C126 "0402ZD106MAT2A" 0402_080 -36.419,131.814 r270 top value=10uF
C127 "0402ZD106MAT2A" 0402_080 -42.588,133.544 r90 top value=10uF
C128 "885012205037" 0402 -41.706,130.148 r270 top value=0.1uF
C129 "885012205037" 0402 -36.538,126.601 r0 top value=0.1uF
C130 "885012205037" 0402 -34.241,116.266 r270 bottom value=0.1uF
C131 "885012205050" FP-885012205050_0402-MFG -5.299,139.081 r180 top value=10nF
C132 "885012205037" 0402 -26.662,124.868 r180 bottom value=0.1uF
C133 "885012205037" 0402 -27.474,115.853 r270 bottom value=0.1uF
C134 "885012205050" FP-885012205050_0402-MFG -14.374,138.244 r90 bottom value=10nF
C135 "885012205050" FP-885012205050_0402-MFG -19.295,138.351 r90 bottom value=10nF
C136 "885012205050" FP-885012205050_0402-MFG -13.552,125.512 r180 bottom value=10nF
C137 "885012205018" FP-885012205018_0402-MFG -15.587,125.512 r180 bottom value=100nF
C138 "885012205018" FP-885012205018_0402-MFG -21.058,128.544 r180 bottom value=100nF
C139 "885012105012" 0402 -9.173,132.466 r90 bottom value=1uF
C140 "885012105012" 0402 -20.718,136.073 r0 bottom value=1uF
C141 "885012205050" FP-885012205050_0402-MFG -20.812,134.81 r180 bottom value=10nF
C142 "885012105012" 0402 -9.173,134.916 r270 bottom value=1uF
C143 "885012205018" FP-885012205018_0402-MFG -16.087,138.202 r90 bottom value=100nF
C144 "885012105012" 0402 -17.661,137.972 r270 bottom value=1uF
C145 "885012205018" FP-885012205018_0402-MFG -7.24,127.097 r90 bottom value=100nF
C146 "CL05C120JB5NNNC" 0402 -5.292,137.037 r90 top value=12pF
C147 "CL05C120JB5NNNC" 0402 -5.276,134.387 r270 top value=12pF
"CE Logo1" "CE Mark" CE_Mark_5mm -33.68,17.424 r180 bottom
FID1 "Fiducial" Fiducial10-20 -2.667,7.417 r180 bottom
FID2 "Fiducial" Fiducial10-20 -54.671,136.355 r180 bottom
FID3 "Fiducial" Fiducial10-20 -54.658,136.385 r0 top
FID4 "Fiducial" Fiducial10-20 -2.667,7.417 r0 top
FID5 "Fiducial" Fiducial10-20 -53.635,7.555 r180 bottom
FID6 "Fiducial" Fiducial10-20 -53.635,7.555 r0 top
J1/J3 "SSQ-110-03-T-D" BoosterPack_40pin_J1J3 -50.791,95.27 r180 bottom locked
J4/J2 "SSQ-110-03-T-D" BoosterPack_40pin_J2J4 -7.611,95.27 r180 bottom locked
J5/J7 "SSQ-110-03-T-D" BoosterPack_40pin_J5J7 -50.791,31.77 r180 bottom locked
J8/J6 "SSQ-110-03-T-D" BoosterPack_40pin_J6J8 -7.611,31.77 r180 bottom locked
J10 "61300621121" Wurth_61300621121 -50.791,66.06 r0 top
J11 "61301021121" WURTH_61301021121 -7.611,55.9 r270 top locked
J12 "61300511121" Wurth_61300511121 -15.704,2.368 r180 top
J13 "61300511121" Wurth_61300511121 -29.819,2.425 r180 top
J14 "61300311121" WURTH_61300311121 -7.188,5.105 r270 top
J15 "HTSW-106-07-G-S" FP-HTSW-106-07-G-S_HDR6-MFG -44.704,2.54 r0 top
J17 "61300211121" WURTH_61300211121 -38.735,13.589 r270 top
J18 "61300211121" WURTH_61300211121 -52.061,111.981 r90 top
J101 "FTSH-107-01-F-DV-K" FP-FTSH-107-01-F-DV-K_HDR14-MFG -19.334,113.938 r180 top
JP1 "TSM-102-01-L-DV" Samtec_TSM-102-01-x-DV -52.416,119.942 r270 top
JP4 "61300411121" WURTH_61300411121 -6.341,74.95 r90 top
JP5 "61300311121" WURTH_61300311121 -52.061,76.22 r90 top locked
JP6 "61300311121" WURTH_61300311121 -7.188,13.589 r90 top
JP7 "61300311121" WURTH_61300311121 -52.061,12.72 r90 top locked
JP8 "61300421121" FP-61300421121_HDR4-MFG -50.791,49.55 r270 top locked
JP9 "61300211121" WURTH_61300211121 -12.776,8.026 r0 top
L1 "BLM21PG221SN1D" 0805_HV -34.722,97.409 r180 bottom value="220 ohm"
L2 "60 ohm" 0805_HV -34.442,42.824 r90 bottom
L3 "60 ohm" 0805_HV -45.428,110.947 r0 bottom
L4 "IHHP1008ABERR47M01" IHHP-1008AB -42.748,16.027 r180 top value=470nH
L5 "TFM252012ALMA1R0MTAA" TFM252012 -34.62,105.512 r0 top value=1uH
LED1 "150080SS75000" WL-SMCW_RED_0805 -52.211,129.182 r0 top value=Red
LED3 "150080VS75000" WL-SMCW_Green_0805 -48.082,15.748 r180 top value="Bright Green"
LED4 "150080SS75000" WL-SMCW_RED_0805 -15.621,86.563 r180 top value=Red
LED5 "LTST-C171GKT" LED_LTST-C171 -19.482,86.533 r180 top value=Green
LED7 "150080SS75000" WL-SMCW_RED_0805 -32.697,131.966 r180 top value=Red
LED8 "LTST-C170TBKT" LTST-C170TBKT_Blue -25.842,140.745 r90 top value=Blue
LED9 "LTST-C170TBKT" LTST-C170TBKT_Blue -27.982,140.736 r90 top value=Blue
Logo1 "Texas Instruments" TI_Stacked_Overlay_Medium -27.418,34.874 r180 bottom
Logo3 "FCC disclaimer" FCC_disclaimer 20.269,-44.044 r180 bottom locked
Logo4 "WEEE logo" WEEE_Minimum -25.502,17.932 r180 bottom
Logo5 "Texas Instruments" TI_Symbol_Overlay_Small -32.736,140.482 r0 top
Logo6 "ETHERCAT LABEL" EtherCAT_label -40.791,75.888 r0 top
M1 "60900213421" Wurth_60900213421 -49.521,49.534 r270 top
M2 "60900213421" Wurth_60900213421 -52.061,49.534 r90 top
M3 "60900213421" Wurth_60900213421 -12.776,8.057 r180 top
M4 "60900213421" Wurth_60900213421 -52.019,111.981 r90 top
M6 "60900213421" Wurth_60900213421 -51.072,120.222 r90 top
M7 "60900213421" Wurth_60900213421 -53.648,120.196 r90 top
MH1 "MTG_NoPads" NPTH125mil#1 -55.871,141.625 r0 top
MH2 "MTG_NoPads" NPTH125mil#1 -2.531,141.625 r0 top
MH3 "MTG_NoPads" NPTH125mil#2 -55.871,34.31 r0 top
MH4 "MTG_NoPads" NPTH125mil#2 -2.531,34.31 r0 top locked
R1 "ERJ-3GEY0R00V" 0603 -12.116,105.791 r180 top value=0
R2 "ERJ-3GEY0R00V" 0603 -12.065,102.972 r180 top value=0
R3 "ERJ-3GEY0R00V" 0603 -12.344,44.323 r180 top value=0
R4 "ERJ-3GEY0R00V" 0603 -12.395,41.3 r180 top value=0
R5 "CRCW04021K00FKED" 0402 -21.784,9.579 r270 top value=1.00k
R6 "CRCW04021K00FKED" 0402 -23.114,9.579 r270 top value=1.00k
R7 "CRCW04021K00FKED" 0402 -24.562,9.579 r270 top value=1.00k
R8 "CRCW04021K00FKED" 0402 -26.568,10.392 r270 top value=1.00k
R9 "CRCW04021K00FKED" 0402 -28.067,10.389 r270 top value=1.00k
R10 "CRCW04021K00FKED" 0402 -30.124,10.392 r270 top value=1.00k
R11 "RC0603FR-07120RL" 0603 -11.354,11.811 r90 top value=120
R12 "CRCW0402680RJNED" 0402 -16.993,97.231 r90 top value=680
R13 "CRCW0402680RJNED" 0402 -18.669,97.231 r90 top value=680
R14 "CRCW040210M0JNED" 0402 -15.376,90.339 r270 top value=10Meg
R15 "CRCW040210M0JNED" 0402 -20.193,90.322 r270 top value=10Meg
R16 "CRCW04023K30JNED" 0402 -17.53,122.65 r270 top value=3.3k
R17 "CRCW06030000Z0EA" 0603 -16.84,94.361 r270 top value=0
R18 "CRCW04022K20JNED" 0402 -38.862,104.084 r180 bottom value=2.2k
R19 "CRCW06030000Z0EA" 0603 -18.855,94.38 r270 top value=0
R20 "CRCW06030000Z0EA" 0603 -18.665,59.491 r270 top value=0
R21 "CRCW06030000Z0EA" 0603 -16.852,61.747 r0 top value=0
R22 "FC0603E50R0BTBST1" 0603 -16.053,59.491 r90 top value=50
R23 "CRCW040210K0JNED" 0402 -43.688,6.883 r0 top value=2.2k
R24 "CRCW040210K0JNED" 0402 -40.996,6.883 r0 top value=2.2k
R25 "CRCW04024K70JNED" 0402 -35.027,109.726 r270 bottom value=4.7k
R26 "RC0402JR-070RL" 0402 -36.15,104.721 r90 bottom value=0
R27 "AC0402FR-0710KL" 0402 -34.208,105.321 r180 bottom value=10.0k
R28 "CRCW04024K70JNED" 0402 -40.499,108.37 r90 bottom value=4.7k
R29 "RC0402JR-070RL" 0402 -38.676,107.66 r180 bottom value=0
R30 "CRCW06030000Z0EA" 0603 -23.317,24.119 r180 bottom value=0
R31 "RC0603FR-0710KL" 0603 -17.323,73.47 r90 top value=10.0k
R32 "RC0402JR-070RL" 0402 -36.891,110.566 r0 bottom value=0
R33 "RC0603FR-0710KL" 0603 -13.437,70.649 r180 top value=10.0k
R34 "CRCW06032K20JNEA" 0603 -23.292,22.428 r180 bottom value=2.2k
R35 "CRCW06030000Z0EA" 0603 -19.888,24.119 r180 bottom value=0
R36 "CRCW06030000Z0EA" 0603 -19.863,22.428 r0 bottom value=0
R37 "RC0402JR-070RL" 0402 -44.934,83.844 r0 top value=0
R38 "RC0402JR-070RL" 0402 -44.934,102.191 r0 top value=0
R39 "RC0402JR-070RL" 0402 -44.934,91.998 r0 top value=0
R40 "RC0402JR-070RL" 0402 -44.934,98.114 r0 top value=0
R41 "CRCW040233R0JNED" 0402 -46.965,73.368 r0 top value=0
R42 "CRCW040233R0JNED" 0402 -47.015,74.495 r0 top value=0
R43 "RC0402JR-070RL" 0402 -44.923,34.389 r0 top value=0
R44 "CRCW04022K20JNED" 0402 -40.31,110.388 r0 bottom value=2.2k
R45 "RC0402JR-070RL" 0402 -44.934,87.921 r0 top value=0
R46 "RC0402JR-070RL" 0402 -44.934,100.152 r0 top value=0
R47 "RC0402JR-070RL" 0402 -44.923,36.41 r0 top value=0
R48 "CRCW040233R0JNED" 0402 -45.593,69.063 r0 top value=0
R49 "CRCW040233R0JNED" 0402 -45.593,70.155 r0 top value=0
R50 "RC0402JR-070RL" 0402 -44.934,89.96 r0 top value=0
R51 "RC0402JR-070RL" 0402 -44.923,26.308 r0 top value=0
R52 "RC0402JR-070RL" 0402 -44.923,24.288 r0 top value=0
R53 "RC0402JR-070RL" 0402 -44.934,85.883 r0 top value=0
R54 "RC0402JR-070RL" 0402 -44.923,38.43 r0 top value=0
R55 "RC0402JR-070RL" 0402 -44.923,30.349 r0 top value=0
R56 "RC0402JR-070RL" 0402 -44.923,28.329 r0 top value=0
R57 "RC0402JR-070RL" 0402 -44.934,96.075 r0 top value=0
R58 "RC0402JR-070RL" 0402 -44.923,32.369 r0 top value=0
R59 "CRCW04022K20JNED" 0402 -7.696,64.872 r90 bottom value=2.2k
R60 "RC0402JR-070RL" 0402 -44.923,20.247 r0 top value=0
R61 "RC0402JR-070RL" 0402 -44.923,22.268 r0 top value=0
R62 "RC0402JR-070RL" 0402 -44.934,94.037 r0 top value=0
R68 "CRCW04021M00FKED" 0402 -48.886,134.712 r0 top value=1.00Meg
R69 "RC0603JR-073KL" 0603 -52.261,131.233 r180 top value=3.0k
R72 "RC0402JR-070RL" 0402 -35.435,99.333 r0 top value=0
R74 "ERJ-3GEY0R00V" 0603 -37.096,116.167 r270 bottom value=0
R76 "ERJ-3GEY0R00V" 0603 -26.023,116.183 r270 bottom value=0
R78 "RC0603JR-075K1L" 0603 -48.241,130.182 r90 top value=5.1k
R81 "RC0603JR-075K1L" 0603 -46.654,130.182 r90 top value=5.1k
R82 "CRCW04021K10JNED" 0402 -49.042,12.72 r270 top value=1.1k
R96 "CRCW0402680RJNED" 0402 -35.173,131.814 r270 top value=680
R97 "ERJ-3GEY0R00V" 0603 -39.155,116.171 r90 bottom value=0
R98 "ERJ-3GEY0R00V" 0603 -40.755,116.171 r90 bottom value=0
R99 "ERJ-3GEY0R00V" 0603 -42.355,116.171 r90 bottom value=0
R100 "ERJ-3GEY0R00V" 0603 -44.039,116.158 r90 bottom value=0
R101 "CRCW04021K00FKED" 0402 -7.251,123.263 r0 top value=1.00k
R102 "CRCW04021K00FKED" 0402 -7.251,122 r0 top value=1.00k
R103 "CRCW04021K00FKED" 0402 -10.615,122.702 r270 top value=1.00k
R104 "CRCW04021K00FKED" 0402 -11.863,122.695 r270 top value=1.00k
R107 "RC0402JR-070RL" 0402 -42.621,14.072 r0 top value=0
R164 "CRCW0402100RJNED" 0402 -6.986,140.745 r270 top value=100
R165 "ERJ-3GEY0R00V" 0603 -29.661,116.266 r90 bottom value=0
R171 "ERJ-3GEY0R00V" 0603 -31.279,116.266 r90 bottom value=0
R172 "RC0402FR-07470RL" 0402 -25.892,137.478 r270 top value=470
R173 "RC0402FR-07470RL" 0402 -27.994,137.498 r270 top value=470
R174 "CRCW040210K0JNED" 0402 -5.267,127.95 r270 top value=10k
R175 "CRCW040210K0JNED" 0402 -5.267,130.624 r270 top value=10k
R176 "CRCW04024K87FKED" 0402 -13.114,122.691 r90 top value=4.87k
R177 "CRCW040251R0JNED" 0402 -5.267,125.276 r90 top value=51
S1 "1188E-1K2-V-TR" SW_1188E -2.277,113.304 r180 top
S2 "CAS-D20TA" SW_CAS-D20TA -26.594,102.133 r0 top
S3 "CAS-D20TA" SW_CAS-D20TA -12.7,74.168 r180 top
S4 "CAS-220TA" SW_CAS-220TA -19.925,42.117 r180 top
S5 "CAS-D20TA" SW_CAS-D20TA -27.829,42.117 r0 top
S6 "CAS-D20TA" SW_CAS-D20TA -46.473,58.09 r180 top
TP1 "TESTPOINT" TP_50MIL-25MILHOLE#1 -34.011,86.436 r0 top
TP2 "TESTPOINT" TP_50MIL-25MILHOLE#1 -28.321,86.38 r90 top
TP3 "TESTPOINT" TP_50MIL-25MILHOLE#1 -34.493,45.669 r0 top
TP4 "TESTPOINT" TP_50MIL-25MILHOLE#1 -34.366,112.039 r0 top
TP5 "TESTPOINT" TP_50MIL-25MILHOLE#1 -33.045,6.883 r0 top
TP6 "TESTPOINT" TP_50MIL-25MILHOLE#1 -24.917,86.385 r0 top
TP7 "TESTPOINT" TP_50MIL-25MILHOLE#1 -13.386,24.282 r90 top
TP8 "TESTPOINT" TP_50MIL-25MILHOLE#1 -15.265,21.295 r90 top
TP9 "TESTPOINT" TP_50MIL-25MILHOLE#2 -42.367,104.292 r180 top
TP10 "TESTPOINT" TP_50MIL-25MILHOLE#2 -38.669,98.679 r180 top
TP11 "TESTPOINT" TP_50MIL-25MILHOLE#3 -32.715,100.83 r180 top
U1 "F29H850TU9SRFS" RFS0144A-MFG -28.744,66.221 r315 top locked
U2 "MSP432E401YTPDT" PDT0128A -15.226,132.735 r0 top locked
U3 "REF5030IDGKT" DGK0008A_N -40.056,45.923 r180 top
U4 "TPD4E004DRYR" DRY0006A -38.684,112.217 r90 top
U5 "TPD4E004DRYR" DRY0006A -24.994,111.633 r90 top
U6 "TS5A23157DGSR" DGS0010A_N -31.064,108.356 r90 top locked
U7 "SN74LVC2G07DBVR" DBV0006A_N -17.905,90.525 r270 top locked
U8 "TS5A23157DGSR" DGS0010A_N -21.311,107.183 r0 top
U9 "TS5A23157DGSR" DGS0010A_N -27.534,108.331 r90 top
U10 "TPS65036" RAY0024B-MFG -38.862,106.197 r0 top locked
U11 "SN74LV4053APWR" PW0016A-MFG -29.769,33.116 r180 top locked
U12 "OPA2320AIDGKR" DGK0008A_N -40.157,50.895 r180 top
U13 "SN74LVC8T245PW" PW0024A_N -23.241,23.139 r270 top locked
U14 "SN74LV4053APWR" PW0016A-MFG -20.752,33.147 r180 top
U15 "TCAN332GDR" D0008A_N -16.466,15.164 r270 top
U16 "TPD4E05U06DQAR" DQA0010A -45.588,134.317 r90 top
U23 "TPS610333DRLR" DRL0008A-MFG -42.812,12.014 r180 top
U25 "TLV70333DBVR" DBV0005A-MFG -39.064,131.84 r0 top
U26 "ISO7741DWR" DW0016B_HV -41.551,119.993 r270 top locked
U27 "ISO7731DWR" DW0016B_HV -30.434,119.993 r270 top locked
USB1 "MUP-U22001" FP-MUP-U22001_CONN_USB_8MM94_8MM0-MFG -46.211,140.635 r180 top locked
Y1 "NX3225GA-16.000M-STD-CRG-1" NDK_NX3225GA -3.034,135.529 r180 top
Y2 "830108207209" FP-830108207209_SMT_CRYSTAL_3MM2_2MM5-MFG -17.069,56.21 r0 top
ZZ1 "These assemblies are ESD sensitive, ESD precautions shall be observed." AssemblyNote -58.337,163.148 r0 top
ZZ2 "These assemblies must be clean and free from flux and all contaminants. Use of no clean flux is not acceptable." AssemblyNote -58.411,160.963 r0 top
ZZ3 "These assemblies must comply with workmanship standards IPC-A-610 Class 2, unless otherwise specified." AssemblyNote -58.395,158.674 r0 top

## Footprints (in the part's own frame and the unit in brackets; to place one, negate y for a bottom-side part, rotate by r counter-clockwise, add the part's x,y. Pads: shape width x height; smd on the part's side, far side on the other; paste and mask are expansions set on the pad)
0402 [mm] "0402 from SM-752 data"
  rect 0.8x0.6 smd: 1(-0.6,0) 2(0.6,0)
  silkscreen extent -1.22,-0.52 1.22,0.52, body extent -0.55,-0.3 0.55,0.3, height 0.6
0402_070 [mil] "SMD, 2-Leads, Body 1.2x0.7mm, Height 0.7mm"
  rect 15x24 smd: 1(-20,0) 2(20,0)
  body extent -24,-14 24,14, height 28
0402_080 [mm] "SMD, 2-Leads, Body 1x0.5mm"
  rect 0.8x0.6 smd: 1(-0.6,0) 2(0.6,0)
  silkscreen extent -1.22,-0.52 1.22,0.52, body extent -0.65,-0.4 0.65,0.4, height 0.8
0603 [mm] "0603 from SM-752 data"
  rect 1x0.95 smd: 1(-0.8,0) 2(0.8,0)
  silkscreen extent -1.52,-0.69 1.52,0.69, body extent -0.87,-0.47 0.87,0.47, height 1
0805_HV [mil] "0805 with 30mil clearance between pads"
  rect 50x63 smd: 1(-40,0) 2(40,0)
  silkscreen extent -74,-40 74,40, body extent -43,-29 43,29, height 57
AssemblyNote [mm] "Assembly Note"
BoosterPack_40pin_J1J3 [mm] "Receptacle, 2.54mm, 10x2, TH"
  rrect6% 1.55x1.55 hole 1.02: 1(1.27,11.43)
  round 1.55 hole 1.02: 2(1.27,8.89) 3(1.27,6.35) 4(1.27,3.81) 5(1.27,1.27) 6(1.27,-1.27) 7(1.27,-3.81) 8(1.27,-6.35) 9(1.27,-8.89) 10(1.27,-11.43) 21(-1.27,11.43) 22(-1.27,8.89) 23(-1.27,6.35) 24(-1.27,3.81) 25(-1.27,1.27) 26(-1.27,-1.27) 27(-1.27,-3.81) 28(-1.27,-6.35) 29(-1.27,-8.89) 30(-1.27,-11.43)
  silkscreen extent -7.62,-12.95 7.62,12.95, body extent -2.48,-12.95 2.48,12.95, height 8.51
BoosterPack_40pin_J2J4 [mm] "Receptacle, 2.54mm, 10x2, TH"
  round 1.55 hole 1.02: 11(-1.27,-11.43) 12(-1.27,-8.89) 13(-1.27,-6.35) 14(-1.27,-3.81) 15(-1.27,-1.27) 16(-1.27,1.27) 17(-1.27,3.81) 18(-1.27,6.35) 19(-1.27,8.89) 20(-1.27,11.43) 31(1.27,-11.43) 32(1.27,-8.89) 33(1.27,-6.35) 34(1.27,-3.81) 35(1.27,-1.27) 36(1.27,1.27) 37(1.27,3.81) 38(1.27,6.35) 39(1.27,8.89) 40(1.27,11.43)
  silkscreen extent -7.62,-12.95 2.48,12.95, body extent -2.48,-12.95 2.48,12.95, height 8.51
BoosterPack_40pin_J5J7 [mm] "Receptacle, 2.54mm, 10x2, TH"
  round 1.55 hole 1.02: 41(1.27,11.43) 42(1.27,8.89) 43(1.27,6.35) 44(1.27,3.81) 45(1.27,1.27) 46(1.27,-1.27) 47(1.27,-3.81) 48(1.27,-6.35) 49(1.27,-8.89) 50(1.27,-11.43) 61(-1.27,11.43) 62(-1.27,8.89) 63(-1.27,6.35) 64(-1.27,3.81) 65(-1.27,1.27) 66(-1.27,-1.27) 67(-1.27,-3.81) 68(-1.27,-6.35) 69(-1.27,-8.89) 70(-1.27,-11.43)
  silkscreen extent -7.62,-12.95 7.62,12.95, body extent -2.48,-12.95 2.48,12.95, height 8.51
BoosterPack_40pin_J6J8 [mm] "Receptacle, 2.54mm, 10x2, TH"
  round 1.55 hole 1.02: 51(-1.27,-11.43) 52(-1.27,-8.89) 53(-1.27,-6.35) 54(-1.27,-3.81) 55(-1.27,-1.27) 56(-1.27,1.27) 57(-1.27,3.81) 58(-1.27,6.35) 59(-1.27,8.89) 60(-1.27,11.43) 71(1.27,-11.43) 72(1.27,-8.89) 73(1.27,-6.35) 74(1.27,-3.81) 75(1.27,-1.27) 76(1.27,1.27) 77(1.27,3.81) 78(1.27,6.35) 79(1.27,8.89) 80(1.27,11.43)
  silkscreen extent -7.62,-12.95 2.48,12.95, body extent -2.48,-12.95 2.48,12.95, height 8.51
CE_Mark_5mm [mm] "Minimum text height for CE Mark"
  silkscreen extent -3.5,-2.5 3.5,2.5
D0008A_N [mm] "SOIC, 8-Leads, Body 4.9x3.9mm, Pitch 1.27mm, IPC Medium Density"
  oval 1.45x0.6 smd: 1(-2.725,1.905) 2(-2.725,0.635) 3(-2.725,-0.635) 4(-2.725,-1.905) 5(2.725,-1.905) 6(2.725,-0.635) 7(2.725,0.635) 8(2.725,1.905)
  silkscreen extent -3.3,-2.5 0.9,2.5, body extent -3,-2.45 3,2.45, height 1.63
DBV0005A-MFG [mm]
  rrect17% 1.1x0.6 smd paste+0 mask+0: 1(-1.3,0.95) 2(-1.3,0) 3(-1.3,-0.95) 4(1.3,-0.95) 5(1.3,0.95)
  silkscreen extent -2.57,-1.53 0.87,1.53, body extent -1.95,-1.78 1.95,1.78, height 0.25
DBV0006A_N [mm] "SOT23, 6-Leads, Body 2.9x1.6mm, Pitch 0.95mm, Lead Span 2.8mm, IPC Medium Density"
  rrect17% 1x0.6 smd: 1(-1.375,0.95) 2(-1.375,0) 3(-1.375,-0.95) 4(1.375,-0.95) 5(1.375,0) 6(1.375,0.95)
  silkscreen extent -1.67,-1.55 0.5,1.55, body extent -1.42,-1.46 1.42,1.46, height 1.12
DGK0008A_N [mm] "TSOP, 8-Leads, Body 3x3mm, Pitch 0.65mm, IPC Medium Density"
  oval 1.35x0.45 smd: 1(-2.225,0.975) 2(-2.225,0.325) 3(-2.225,-0.325) 4(-2.225,-0.975) 5(2.225,-0.975) 6(2.225,-0.325) 7(2.225,0.325) 8(2.225,0.975)
  silkscreen extent -2.75,-1.55 0.95,1.55, body extent -2.45,-1.5 2.45,1.5, height 0.96
DGS0010A_N [mm] "TSSOP, 10-Leads, Body 3x3mm, Pitch 0.5mm, IPC Medium Density"
  oval 1.35x0.3 smd: 1(-2.225,1) 2(-2.225,0.5) 3(-2.225,0) 4(-2.225,-0.5) 5(-2.225,-1) 6(2.225,-1) 7(2.225,-0.5) 8(2.225,0) 9(2.225,0.5) 10(2.225,1)
  silkscreen extent -2.75,-1.55 0.9,1.55, body extent -2.45,-1.5 2.45,1.5, height 0.96
DQA0010A [mm] "SON, 10-Leads, Body 1x2.5mm, Pitch 0.5mm, TI Recommended"
  rrect50% 0.565x0.2 smd: 1(-0.417,1) 2(-0.418,0.5) 4(-0.418,-0.5) 5(-0.418,-1) 6(0.417,-1) 7(0.417,-0.5) 9(0.417,0.5) 10(0.417,1)
  rrect25% 0.565x0.4 smd: 3(-0.418,0) 8(0.417,0)
  rrect28% 0.565x0.36 on Top Paste: 3(-0.418,0) 8(0.417,0)
  silkscreen extent -0.67,-1.45 0.55,1.45, body extent -0.55,-1.3 0.55,1.3, height 0.56
DRL0008A-MFG [mm]
  rrect33% 0.67x0.3 smd paste+0 mask+0: 1(-0.74,0.75) 2(-0.74,0.25) 3(-0.74,-0.25) 4(-0.74,-0.75) 5(0.74,-0.75) 6(0.74,-0.25) 7(0.74,0.25) 8(0.74,0.75)
  silkscreen extent -1.77,-1.28 0.65,1.28, body extent -1.17,-1.35 1.17,1.35, height 0.25
DRY0006A [mm] "USON-6"
  rrect67% 0.45x0.3 smd: 1(-0.275,0.5)
  rrect67% 0.4x0.3 smd: 2(-0.3,0) 3(-0.3,-0.5) 4(0.3,-0.5) 5(0.3,0) 6(0.3,0.5)
  body extent -0.5,-0.72 0.5,0.73, height 0.58
DW0016B_HV [mm] "SOIC-16, HV/isolation option"
  rrect17% 1.65x0.6 smd: 1(-4.875,4.445) 2(-4.875,3.175) 3(-4.875,1.905) 4(-4.875,0.635) 5(-4.875,-0.635) 6(-4.875,-1.905) 7(-4.875,-3.175) 8(-4.875,-4.445) 9(4.875,-4.445) 10(4.875,-3.175) 11(4.875,-1.905) 12(4.875,-0.635) 13(4.875,0.635) 14(4.875,1.905) 15(4.875,3.175) 16(4.875,4.445)
  body extent -5.17,-5.15 5.17,5.15, height 2.59
EtherCAT_label [mm] "ETHERCAT_LABEL"
FCC_disclaimer [mm]
Fiducial10-20 [mm]
  round 1 smd mask+0.5: 1(0,0)
  Top Signal keep-out circle w1.178: c0,0 r0.5
FP-61300421121_HDR4-MFG [mm]
  rrect6% 1.7x1.7 hole 1.1: 1(-1.27,-1.27)
  round 1.7 hole 1.1: 2(-1.27,1.27) 3(1.27,-1.27) 4(1.27,1.27)
  silkscreen extent -2.69,-3.22 2.69,2.62, body extent -2.79,-2.72 2.79,2.72, height 0.25
FP-830108207209_SMT_CRYSTAL_3MM2_2MM5-MFG [mm]
  rrect9% 1.4x1.15 smd paste+0 mask+0: 1(-1.1,-0.8) 2(1.1,-0.8) 3(1.1,0.8) 4(-1.1,0.8)
  silkscreen extent -1.22,-2.05 0,1.35, body extent -1.9,-1.48 1.9,1.48, height 0.25
FP-885012205018_0402-MFG [mm]
  rrect20% 0.5x0.5 smd paste+0 mask+0: 1(-0.5,0) 2(0.5,0)
  silkscreen extent -0.5,-0.63 0.5,0.63, body extent -0.5,-0.25 0.5,0.25, height 0.55
FP-885012205050_0402-MFG [mm]
  rrect20% 0.5x0.5 smd paste+0 mask+0: 1(-0.5,0) 2(0.5,0)
  silkscreen extent -0.53,-0.63 0.53,0.63, body extent -0.85,-0.38 0.85,0.38, height 0.25
FP-885012205064_0402-MFG [mm]
  rrect20% 0.5x0.5 smd paste+0 mask+0: 1(-0.5,0) 2(0.5,0)
  silkscreen extent -0.53,-0.63 0.53,0.63, body extent -0.85,-0.38 0.85,0.38, height 0.25
FP-CC0603KRX5R6BB106_0603-MFG [mm]
  rrect13% 0.8x0.9 smd paste+0 mask+0: 1(-0.75,0) 2(0.75,0)
  silkscreen extent -0.85,-0.87 0.85,0.87, body extent -0.8,-0.4 0.8,0.4, height 1
FP-CGA3E3X7S1A225K080AB_0603-MFG [mm]
  rrect14% 0.7x0.7 smd paste+0 mask+0: 1(-0.7,0) 2(0.7,0)
  silkscreen extent -0.95,-0.73 0.95,0.73, body extent -0.8,-0.4 0.8,0.4, height 1.1
FP-CGA4J3X7S1A106K125AE_0805-MFG [mm]
  rrect13% 0.8x1.05 smd paste+0 mask+0: 1(-0.925,0) 2(0.925,0)
  silkscreen extent -0.15,-0.75 0.15,0.75, body extent -1.2,-0.62 1.2,0.63, height 1.5
FP-FTSH-107-01-F-DV-K_HDR14-MFG [mm]
  rrect14% 0.74x2.79 smd paste+0 mask+0: 1(-3.81,-2.035) 2(-3.81,2.035) 3(-2.54,-2.035) 4(-2.54,2.035) 5(-1.27,-2.035) 6(-1.27,2.035) 7(0,-2.035) 8(0,2.035) 9(1.27,-2.035) 10(1.27,2.035) 11(2.54,-2.035) 12(2.54,2.035) 13(3.81,-2.035) 14(3.81,2.035)
  silkscreen extent -4.51,-4.11 4.51,0.27, body extent -4.61,-3.53 4.61,3.53, height 0.25
FP-GCM1555C1H201FA16D_0402-MFG [mm] "0402 from SM-752 data"
  rect 0.8x0.6 smd: 1(-0.6,0) 2(0.6,0)
  silkscreen extent -1.22,-0.52 1.22,0.52, body extent -0.55,-0.3 0.55,0.3, height 0.6
FP-HTSW-106-07-G-S_HDR6-MFG [mm]
  rrect6% 1.57x1.57 hole 1.02 paste-2539.97 mask+0: 1(-6.35,0)
  round 1.57 hole 1.02 paste-2539.97 mask+0: 2(-3.81,0) 3(-1.27,0) 4(1.27,0) 5(3.81,0) 6(6.35,0)
  silkscreen extent -8.33,-1.27 7.68,1.27, body extent -7.78,-1.37 7.78,1.37, height 0.25
FP-MUP-U22001_CONN_USB_8MM94_8MM0-MFG [mm]
  rrect100% 0.6x1.9 hole 1.9 slot 0.6 at 0 deg: 1(-4.32,3.35) 2(4.32,3.35)
  round 1.207 smd: 1(-4.25,2.92) 2(4.25,2.92)
  round 1.207 smd far side: 1(-4.25,2.92) 2(4.25,2.92)
  rrect100% 1.25x0.7 hole 0.7 slot 1.25 at 0 deg: 1(-3.995,2.75) 2(3.995,2.75)
  rrect100% 0.7x1.5 hole 1.5 slot 0.7 at 0 deg: 3(-5.85,-1.95) 4(5.85,-1.95)
  round 1.17 smd far side: 3(-5.85,-1.625) 4(5.85,-1.625)
  round 1.17 smd: 3(-5.85,-1.625) 4(5.85,-1.625)
  rrect37% 0.27x0.9 smd: A1(-2.625,4.05) A2(-2.125,4.05) A3(-1.625,4.05) A4(-1.125,4.05) A5(-0.625,4.05) A6(-0.125,4.05) A7(0.375,4.05) A8(0.875,4.05) A9(1.375,4.05) A10(1.875,4.05) A11(2.375,4.05) A12(2.875,4.05)
  rrect37% 0.27x0.8 smd: B1(2.625,2.45) B2(2.125,2.45) B3(1.625,2.45) B4(1.125,2.45) B5(0.625,2.45) B6(0.125,2.45) B7(-0.375,2.45) B8(-0.875,2.45) B9(-1.375,2.45) B10(-1.875,2.45) B11(-2.375,2.45) B12(-2.875,2.45)
  Top Signal region: 3.72,3.35 3.72,4.05 3.72,4.169 3.811,4.39 3.98,4.559 4.201,4.65 4.32,4.65 4.439,4.65 4.66,4.559 4.829,4.39 4.92,4.169 4.92,4.05 4.92,4.05 4.92,2.85 4.92,2.731 4.829,2.51 4.66,2.341 4.439,2.25 4.32,2.25 4.32,2.25 3.82,2.25 3.711,2.25 3.508,2.334 3.354,2.488 3.27,2.691 3.27,2.8 3.268,2.898 3.332,3.082 3.456,3.233 3.624,3.332 3.72,3.35 3.72,3.35
  Top Signal region: -3.72,3.35 -3.72,4.05 -3.72,4.169 -3.811,4.39 -3.98,4.559 -4.201,4.65 -4.32,4.65 -4.439,4.65 -4.66,4.559 -4.829,4.39 -4.92,4.169 -4.92,4.05 -4.92,4.05 -4.92,2.85 -4.92,2.731 -4.829,2.51 -4.66,2.341 -4.439,2.25 -4.32,2.25 -4.32,2.25 -3.82,2.25 -3.711,2.25 -3.508,2.334 -3.354,2.488 -3.27,2.691 -3.27,2.8 -3.268,2.898 -3.332,3.082 -3.456,3.233 -3.624,3.332 -3.72,3.35
  Top Signal region: 6.5,-2.349 6.5,-2.472 6.411,-2.701 6.244,-2.882 6.023,-2.99 5.9,-2.999 5.833,-3.004 5.699,-2.987 5.572,-2.942 5.457,-2.873 5.358,-2.781 5.281,-2.672 5.227,-2.548 5.2,-2.416 5.2,-2.349 5.2,-2.349 5.2,-0.749 5.2,-0.65 5.276,-0.466 5.417,-0.325 5.601,-0.249 5.7,-0.249 5.7,-0.249 6,-0.249 6.099,-0.249 6.283,-0.325 6.424,-0.466 6.5,-0.65 6.5,-0.749 6.5,-0.749
  Top Signal region: -6.5,-2.349 -6.5,-2.472 -6.411,-2.701 -6.244,-2.882 -6.023,-2.99 -5.9,-2.999 -5.9,-2.999 -5.833,-3.004 -5.699,-2.987 -5.572,-2.942 -5.457,-2.873 -5.358,-2.781 -5.281,-2.672 -5.227,-2.548 -5.2,-2.416 -5.2,-2.349 -5.2,-2.349 -5.2,-0.749 -5.2,-0.65 -5.276,-0.466 -5.417,-0.325 -5.601,-0.249 -5.7,-0.249 -5.7,-0.249 -6,-0.249 -6.099,-0.249 -6.283,-0.325 -6.424,-0.466 -6.5,-0.65 -6.5,-0.749 -6.5,-0.749
  Bottom Signal region: 3.72,3.35 3.72,4.05 3.72,4.169 3.811,4.39 3.98,4.559 4.201,4.65 4.32,4.65 4.439,4.65 4.66,4.559 4.829,4.39 4.92,4.169 4.92,4.05 4.92,4.05 4.92,2.85 4.92,2.731 4.829,2.51 4.66,2.341 4.439,2.25 4.32,2.25 4.32,2.25 3.82,2.25 3.711,2.25 3.508,2.334 3.354,2.488 3.27,2.691 3.27,2.8 3.268,2.898 3.332,3.082 3.456,3.233 3.624,3.332 3.72,3.35
  Bottom Signal region: -3.72,3.35 -3.72,4.05 -3.72,4.169 -3.811,4.39 -3.98,4.559 -4.201,4.65 -4.32,4.65 -4.439,4.65 -4.66,4.559 -4.829,4.39 -4.92,4.169 -4.92,4.05 -4.92,4.05 -4.92,2.85 -4.92,2.731 -4.829,2.51 -4.66,2.341 -4.439,2.25 -4.32,2.25 -4.32,2.25 -3.82,2.25 -3.711,2.25 -3.508,2.334 -3.354,2.488 -3.27,2.691 -3.27,2.8 -3.268,2.898 -3.332,3.082 -3.456,3.233 -3.624,3.332 -3.72,3.35
  Bottom Signal region: 6.5,-2.349 6.5,-2.472 6.411,-2.701 6.244,-2.882 6.023,-2.99 5.9,-2.999 5.833,-3.004 5.699,-2.987 5.572,-2.942 5.457,-2.873 5.358,-2.781 5.281,-2.672 5.227,-2.548 5.2,-2.416 5.2,-2.349 5.2,-2.349 5.2,-0.749 5.2,-0.65 5.276,-0.466 5.417,-0.325 5.601,-0.249 5.7,-0.249 5.7,-0.249 6,-0.249 6.099,-0.249 6.283,-0.325 6.424,-0.466 6.5,-0.65 6.5,-0.749 6.5,-0.749
  Bottom Signal region: -6.5,-2.349 -6.5,-2.472 -6.411,-2.701 -6.244,-2.882 -6.023,-2.99 -5.9,-2.999 -5.833,-3.004 -5.699,-2.987 -5.572,-2.942 -5.457,-2.873 -5.358,-2.781 -5.281,-2.672 -5.227,-2.548 -5.2,-2.416 -5.2,-2.349 -5.2,-2.349 -5.2,-0.749 -5.2,-0.65 -5.276,-0.466 -5.417,-0.325 -5.601,-0.249 -5.7,-0.249 -5.7,-0.249 -6,-0.249 -6.099,-0.249 -6.283,-0.325 -6.424,-0.466 -6.5,-0.65 -6.5,-0.749 -6.5,-0.749
  Keep-Out Layer lines w0.2: 4.7,-3.5 4.7,0.75 ccw(c4.7,1.25) 5.2,1.25 ccw(c4.7,1.25) 4.7,1.75 -4.7,1.75 ccw(c-4.7,1.25) -5.2,1.25 ccw(c-4.7,1.25) -4.7,0.75 -4.7,-3.5
  silkscreen extent -6,0.13 6,5.17, body extent -6.6,-4.23 6.6,4.75, height 0.25
IHHP-1008AB [mm] "VISHAY"
  rrect12% 0.8x2.2 smd: 1(-1,0) 2(1,0)
  silkscreen extent -0.4,-1.2 0.4,1.2, body extent -1.35,-1.1 1.35,1.1, height 1.2
LED_LTST-C171 [mm] "LITE-ON"
  rect 1.2x1.2 smd: 1(-1.05,0) 2(1.05,0)
  silkscreen extent -1.6,-1 2.2,1, body extent -1.05,-0.67 1.05,0.68, height 0.8
LTST-C170TBKT_Blue [mm] "LITE-ON"
  rect 1.2x1.2 smd: 1(-1.05,0) 2(1.05,0)
  silkscreen extent -1.6,-1 2.2,1, body extent -1.05,-0.67 1.05,0.67, height 1.2
NDK_NX3225GA [mm] "NDK"
  rect 1.2x1.4 smd: 1(-0.8,1.1) 2(-0.8,-1.1) 3(0.8,-1.1) 4(0.8,1.1)
  silkscreen extent -1.9,-0.1 1.4,2, body extent -1.3,-1.65 1.3,1.65, height 0.9
NPTH125mil#1 [mil]
  round 120 hole 125 unplated: 1(0,0)
NPTH125mil#2 [mil]
  round 120 hole 125 unplated: 1(0,-1249.64)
